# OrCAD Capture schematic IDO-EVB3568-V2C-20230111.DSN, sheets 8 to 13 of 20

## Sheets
8 P08. SPK+MIC: size A3; title: IDO-EVB3568-V2; note: SPK + MIC
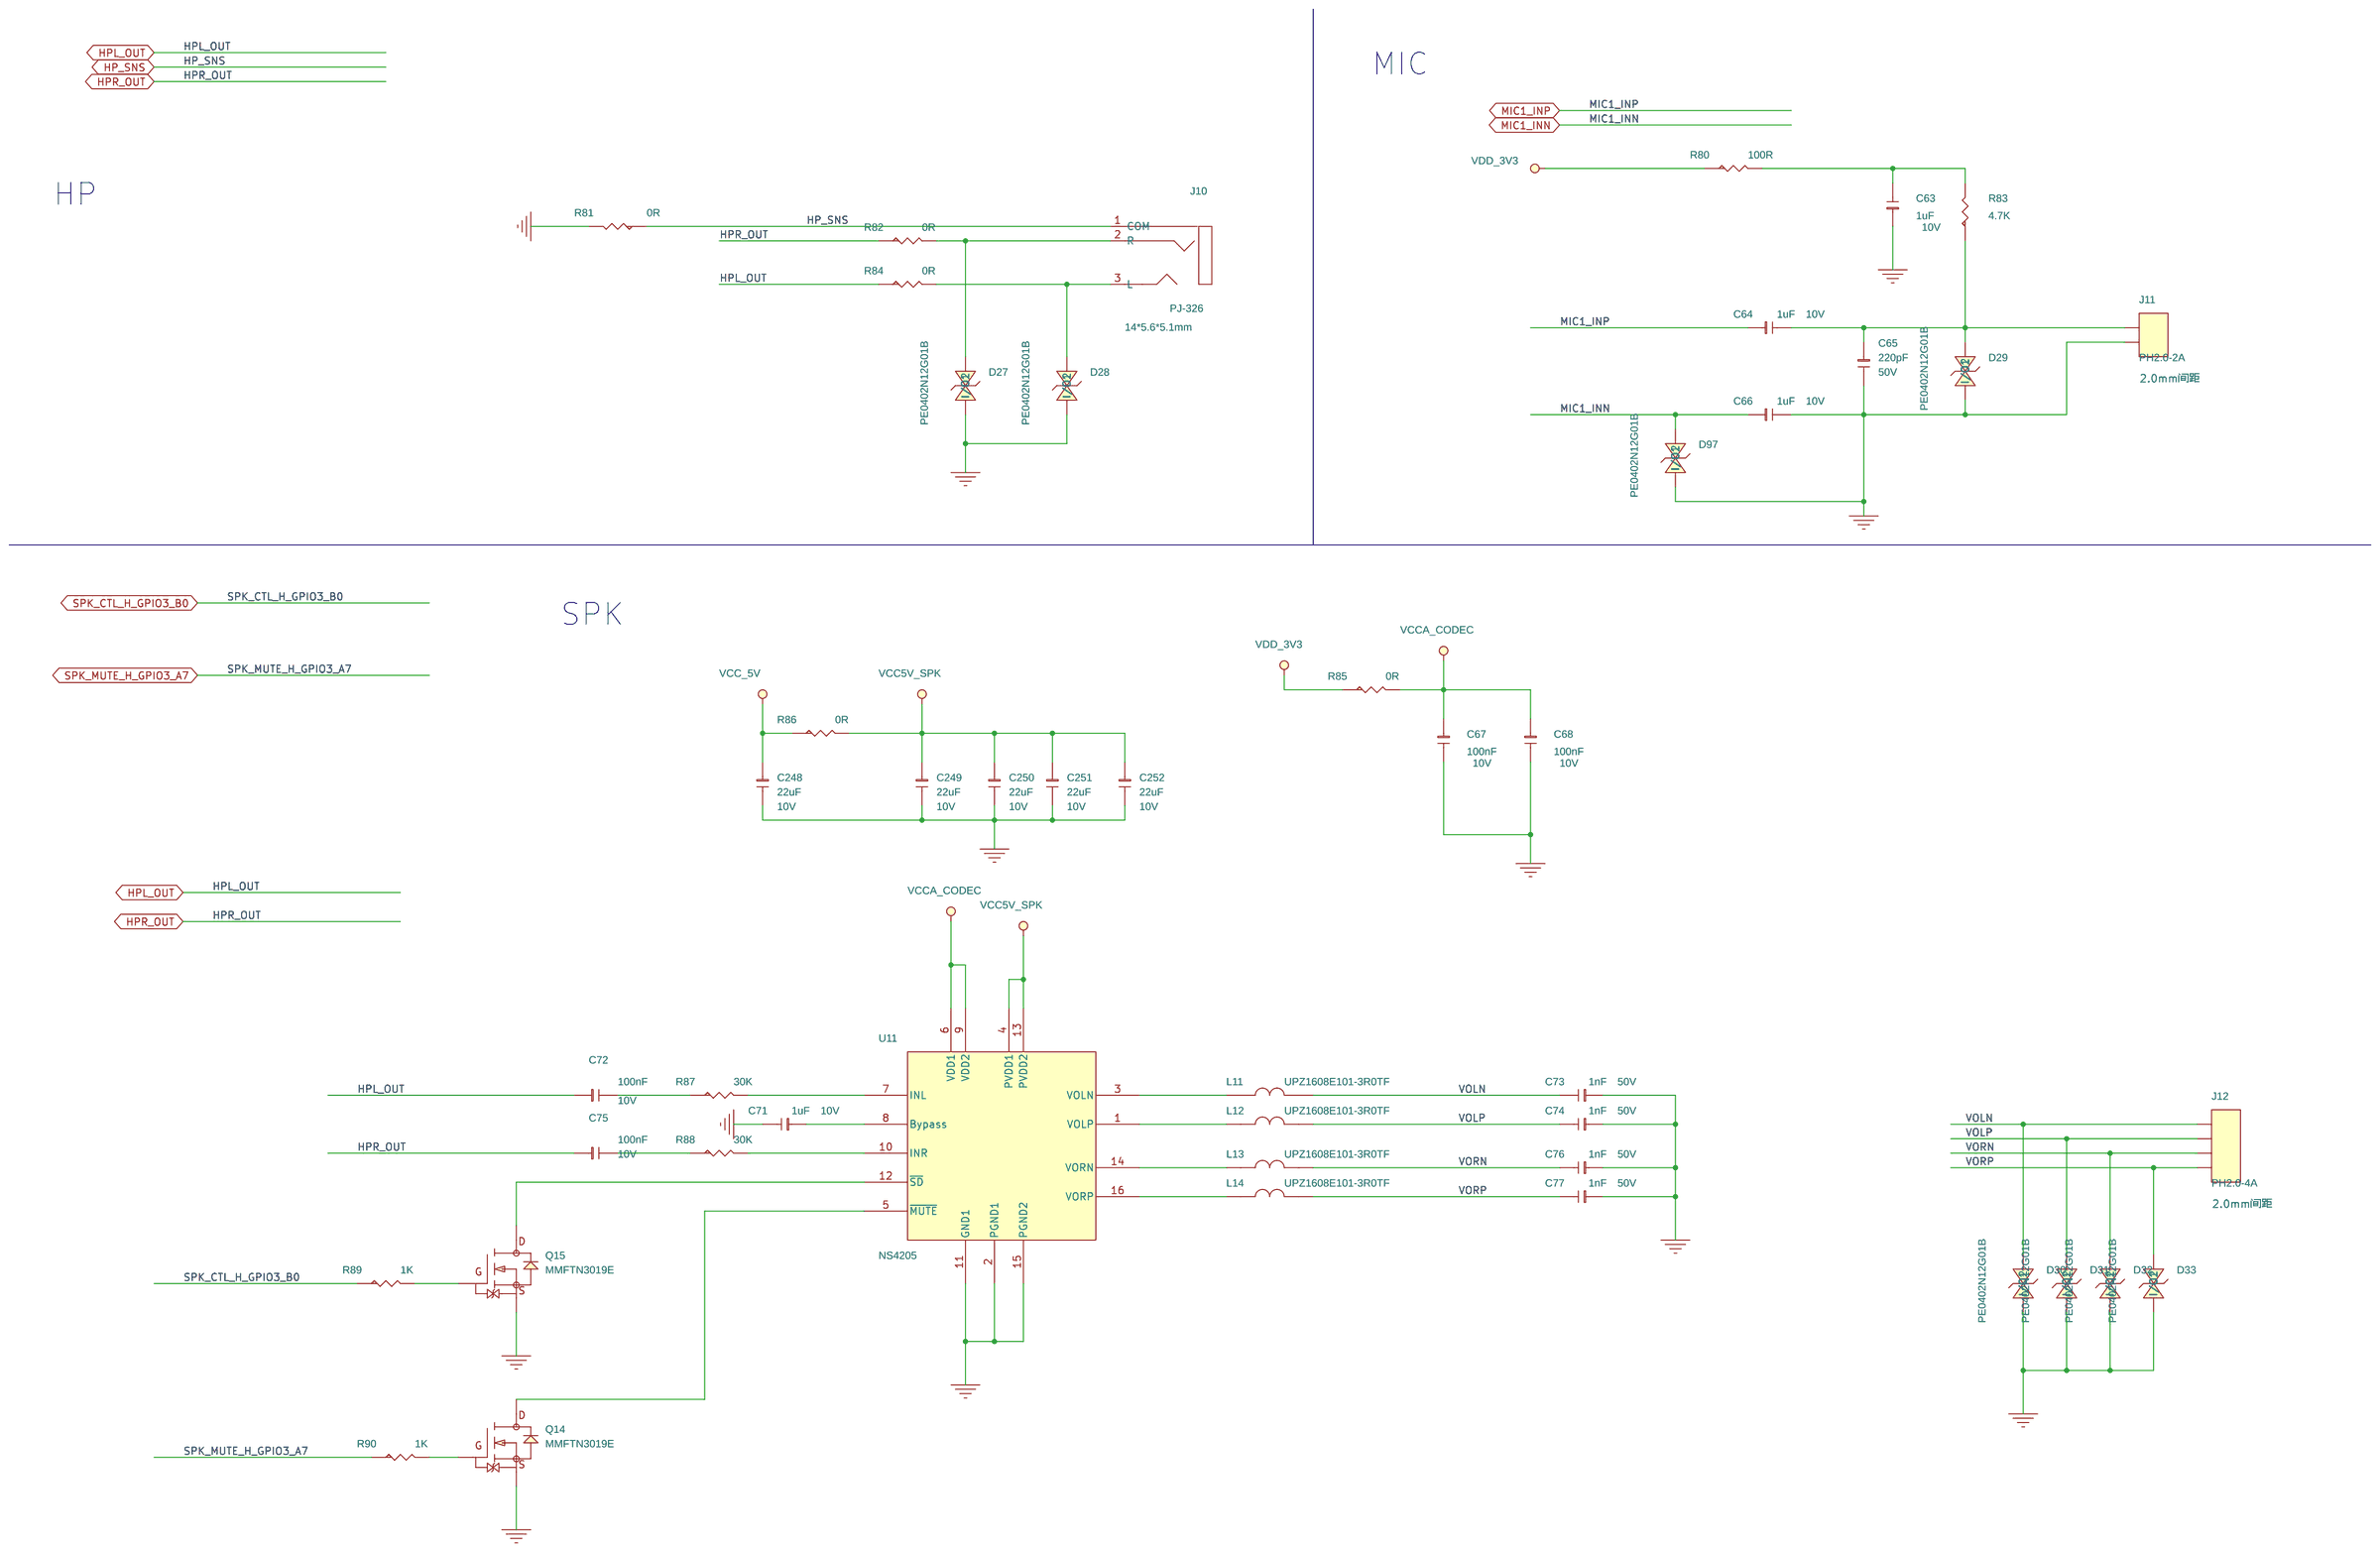
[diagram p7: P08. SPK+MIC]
9 P09. VO-MIPI-TX1: size A4; title: IDO-EVB3568-V2; note: VO-LCM_MIPI_DSI_TX1
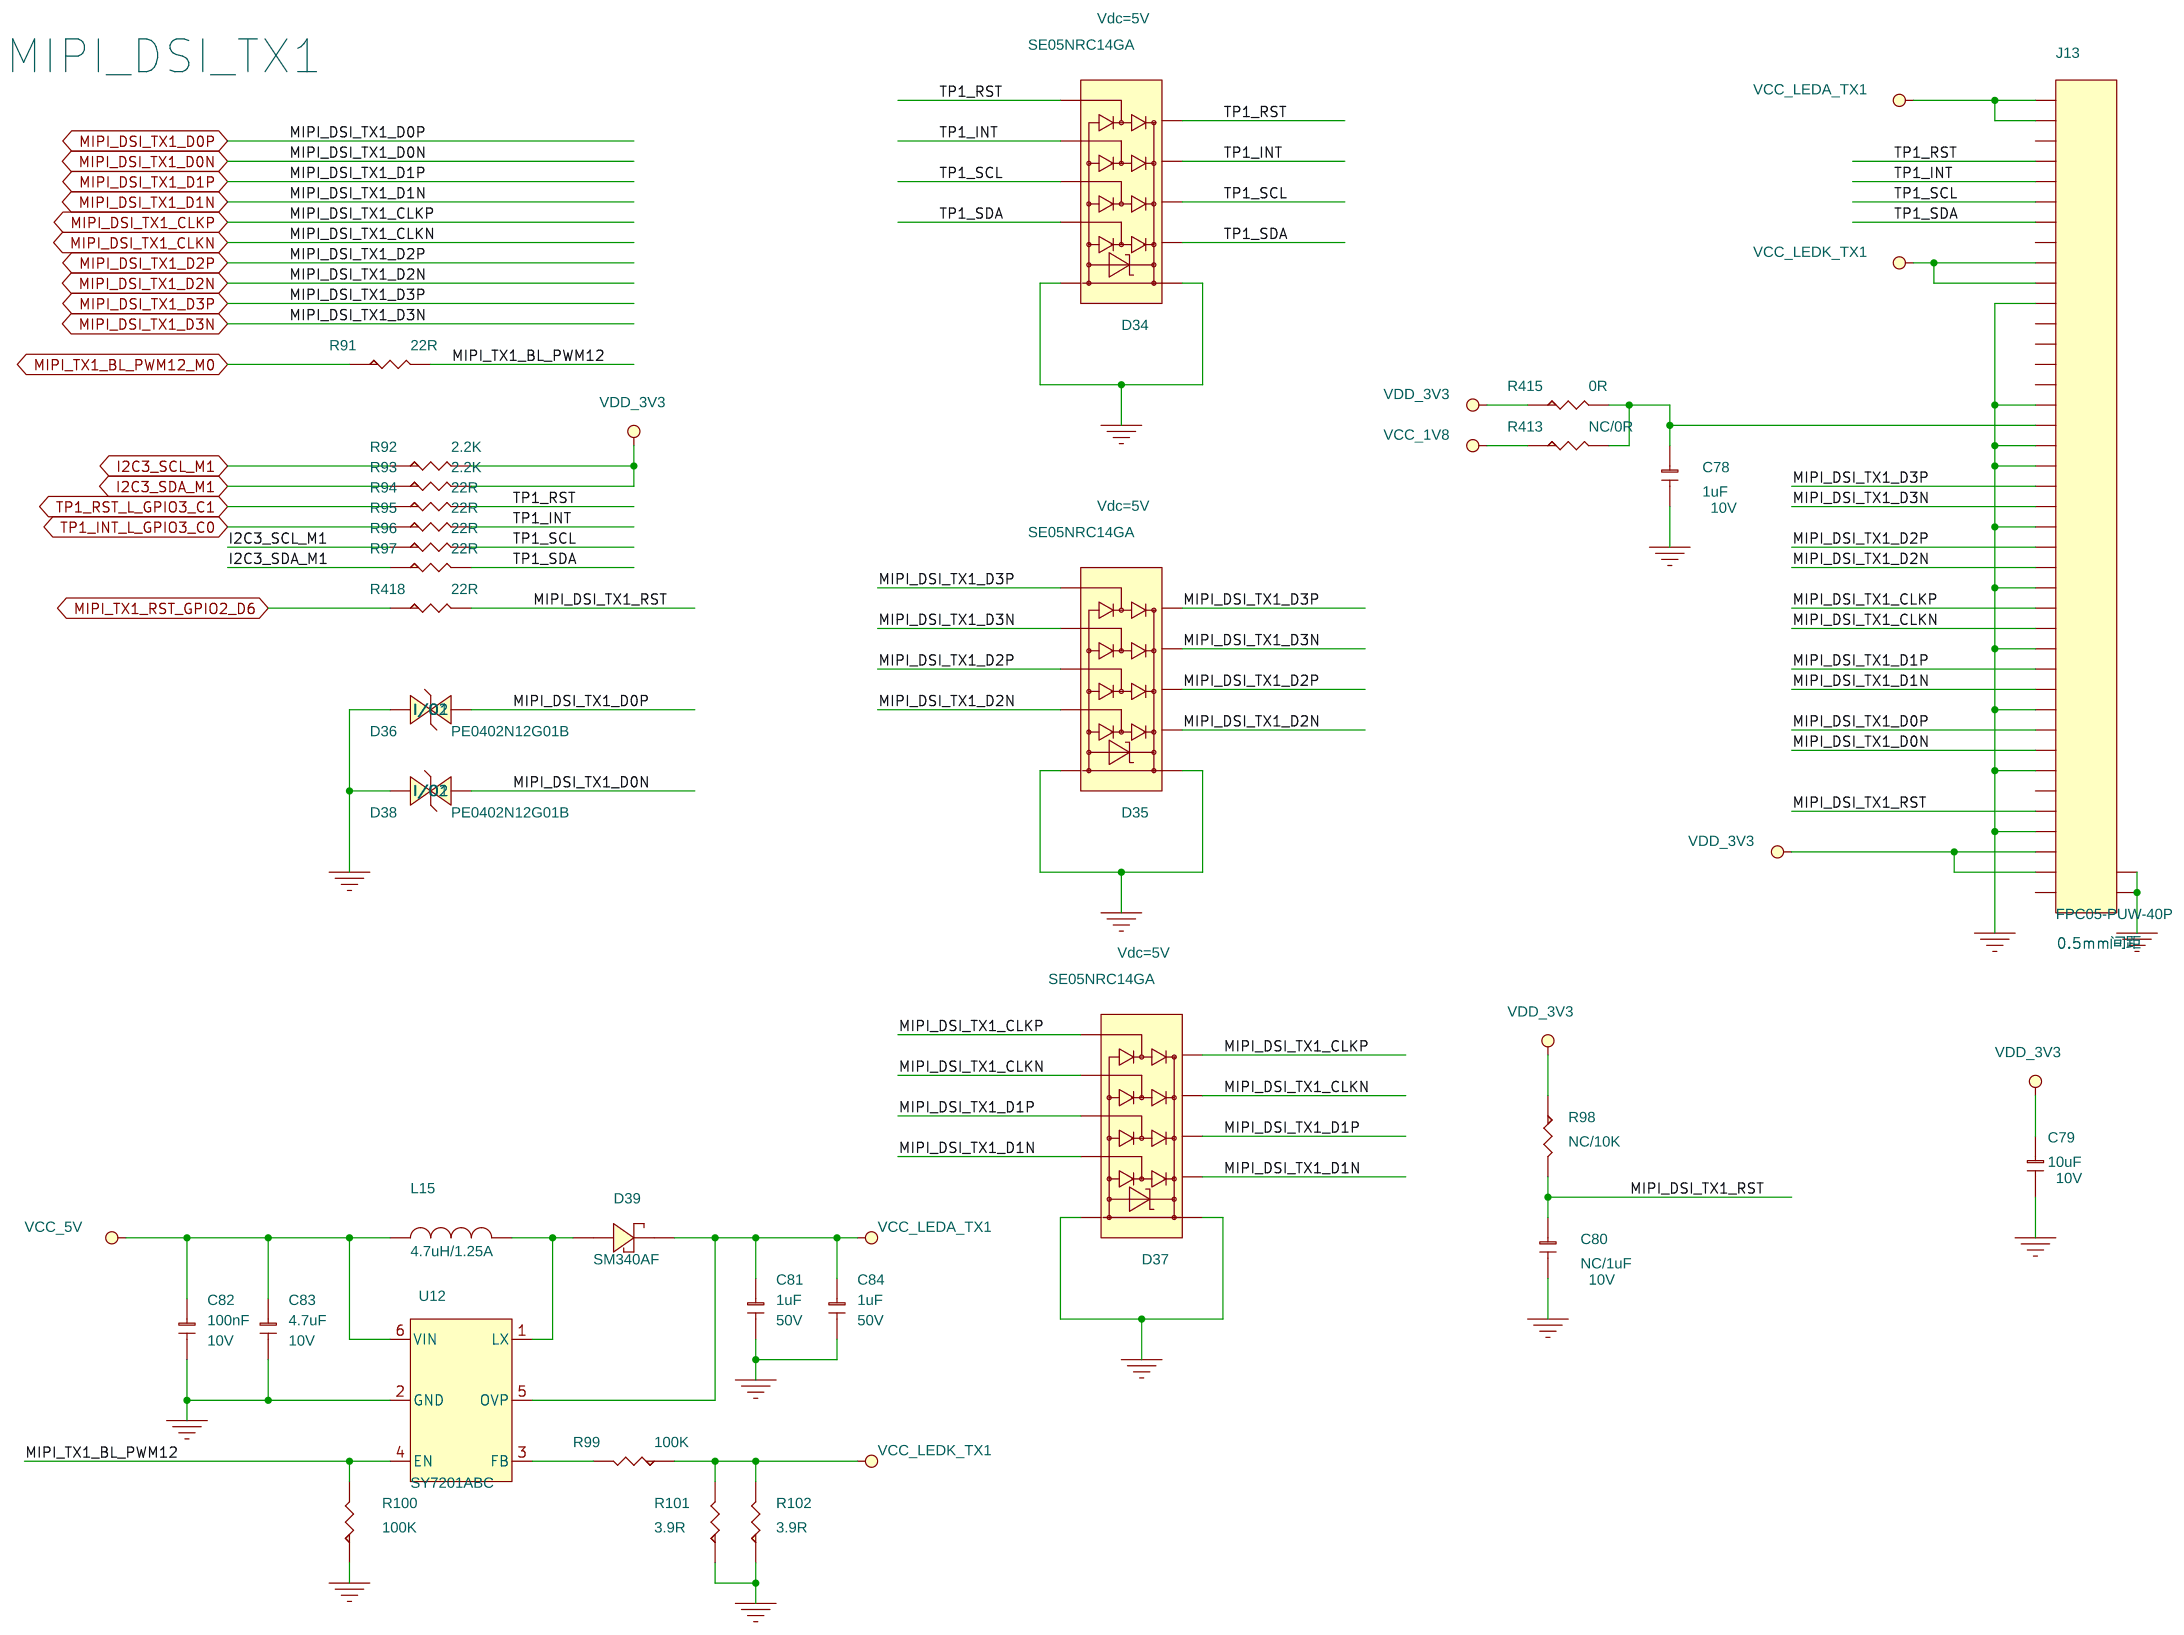
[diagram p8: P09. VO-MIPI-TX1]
10 P10. VO-HDMI2.0 TX: size A4; title: IDO-EVB3568-V2; note: VO-HDMI
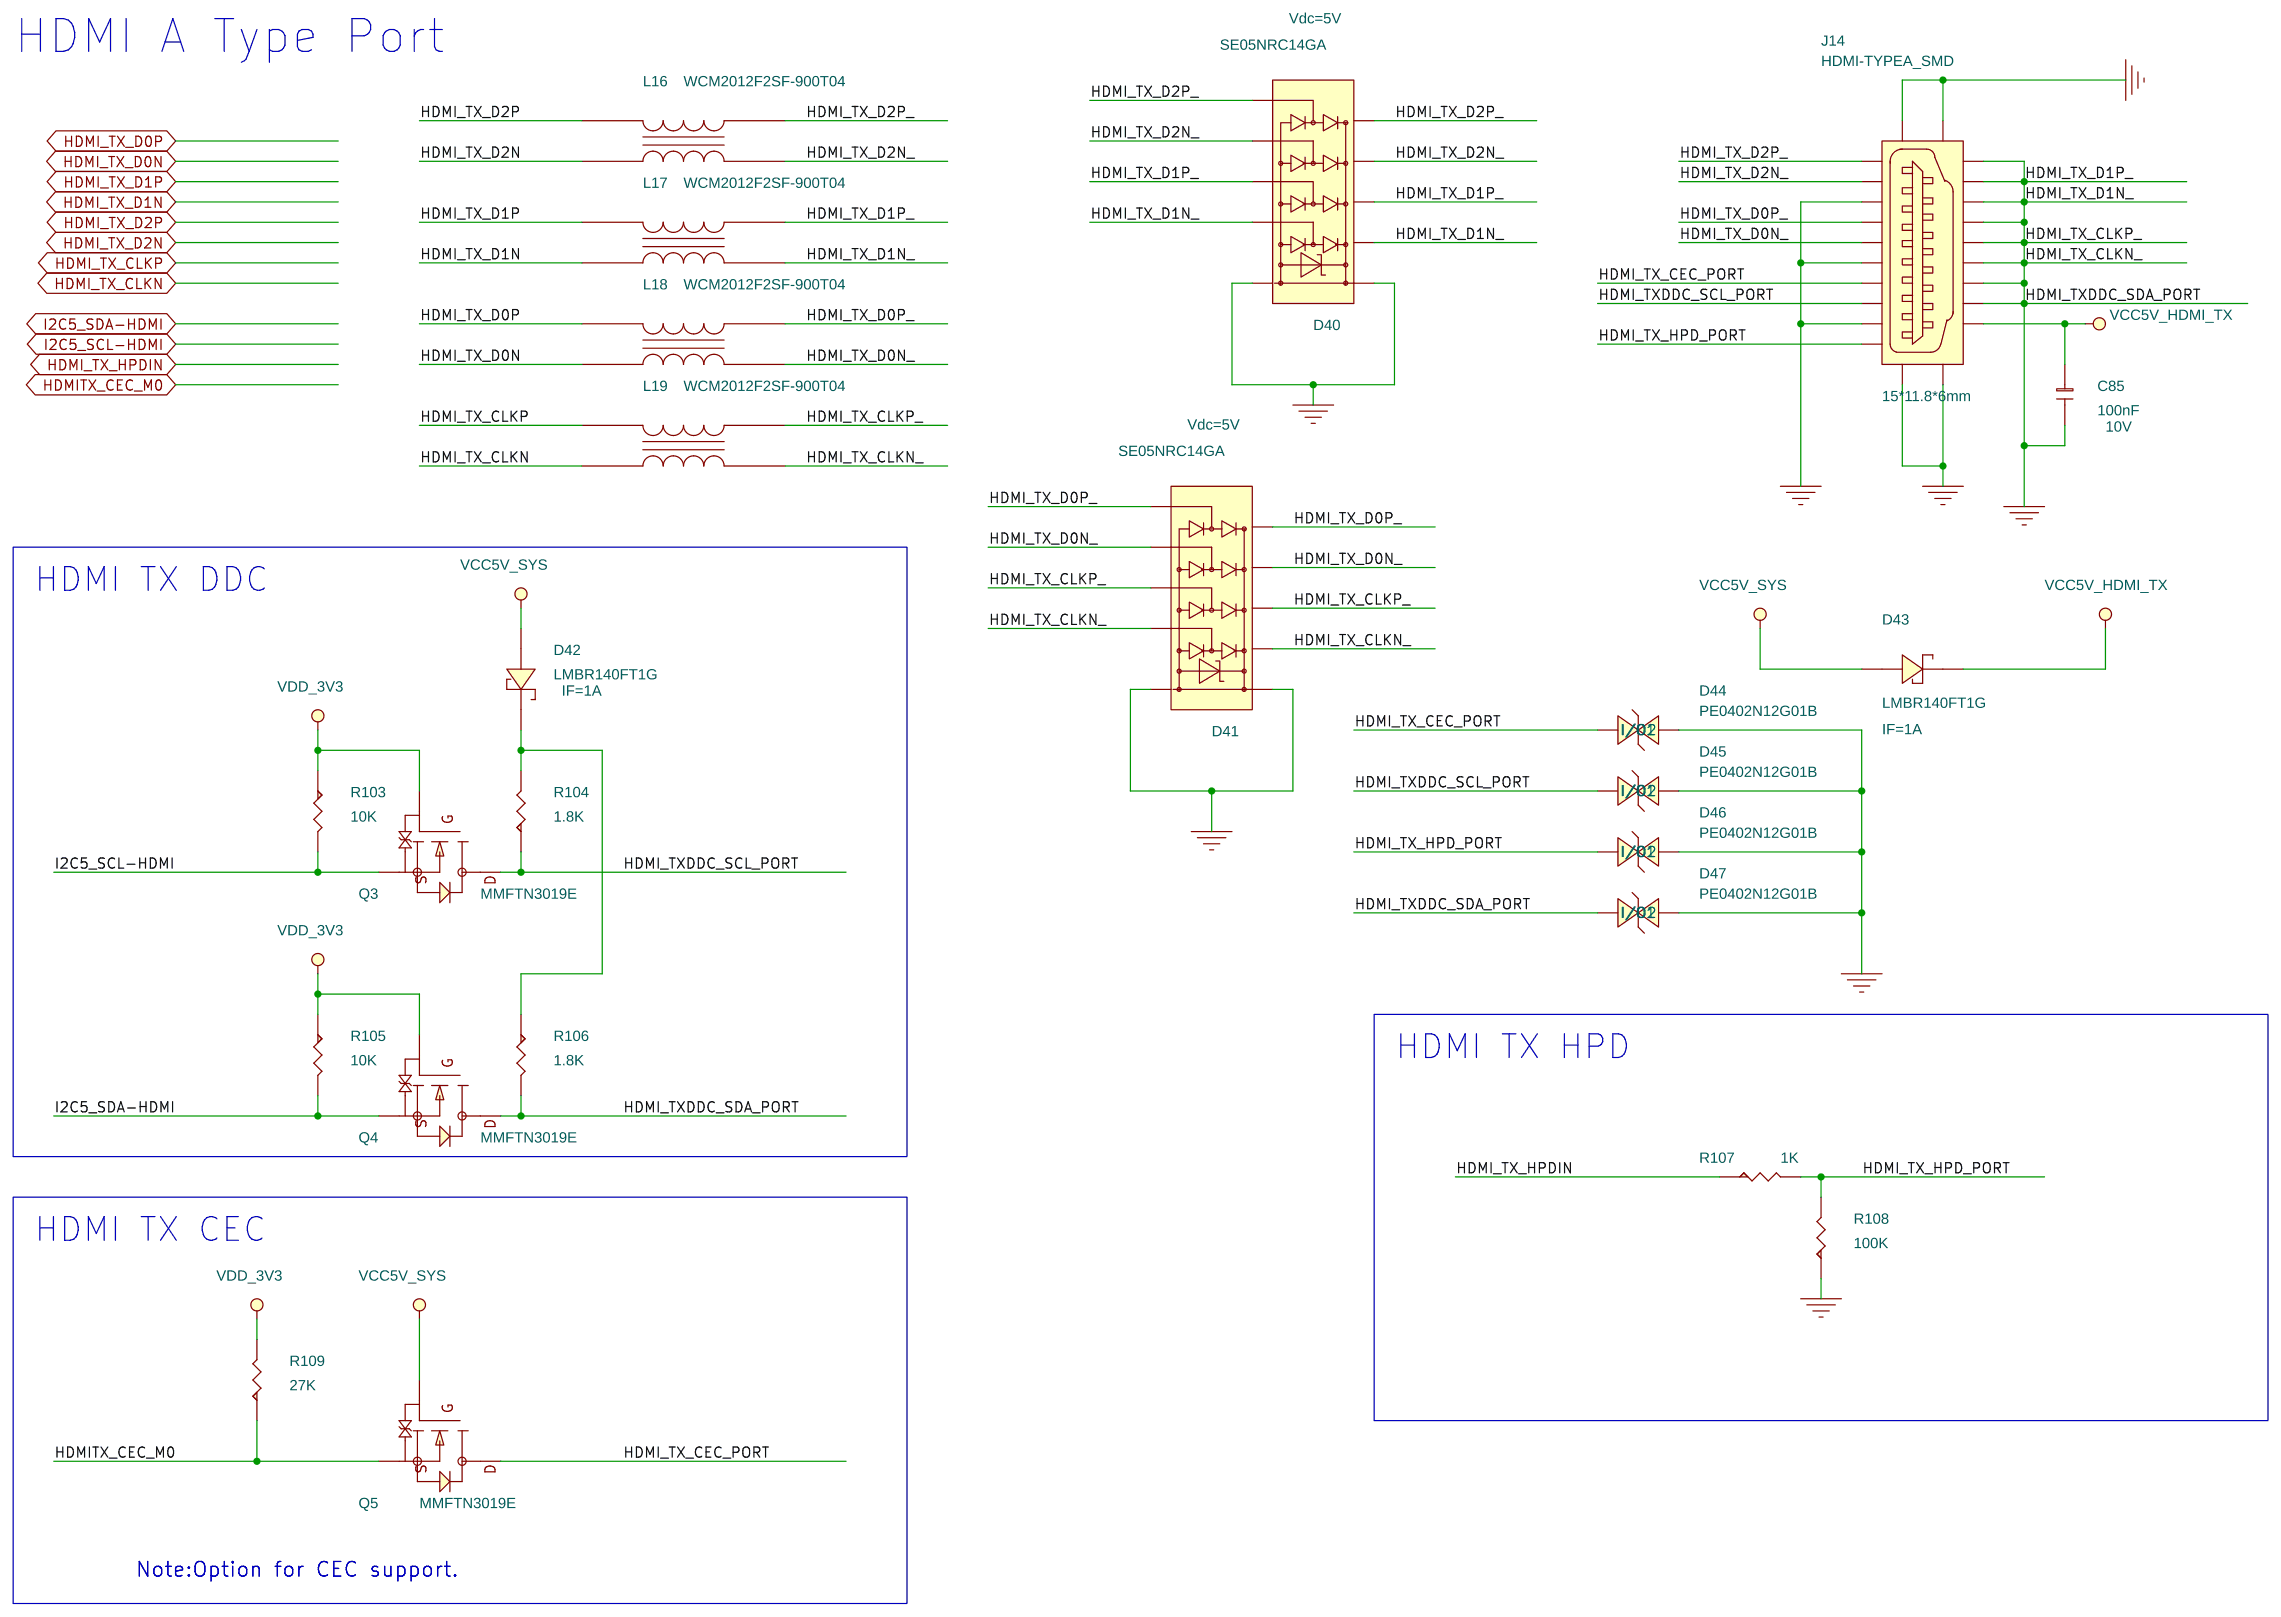
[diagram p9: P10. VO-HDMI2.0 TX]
11 P11. VO-LCM_LVDS_TX0: size A2; title: IDO-EVB3568-V2; note: VO-LCM_LVDS TX
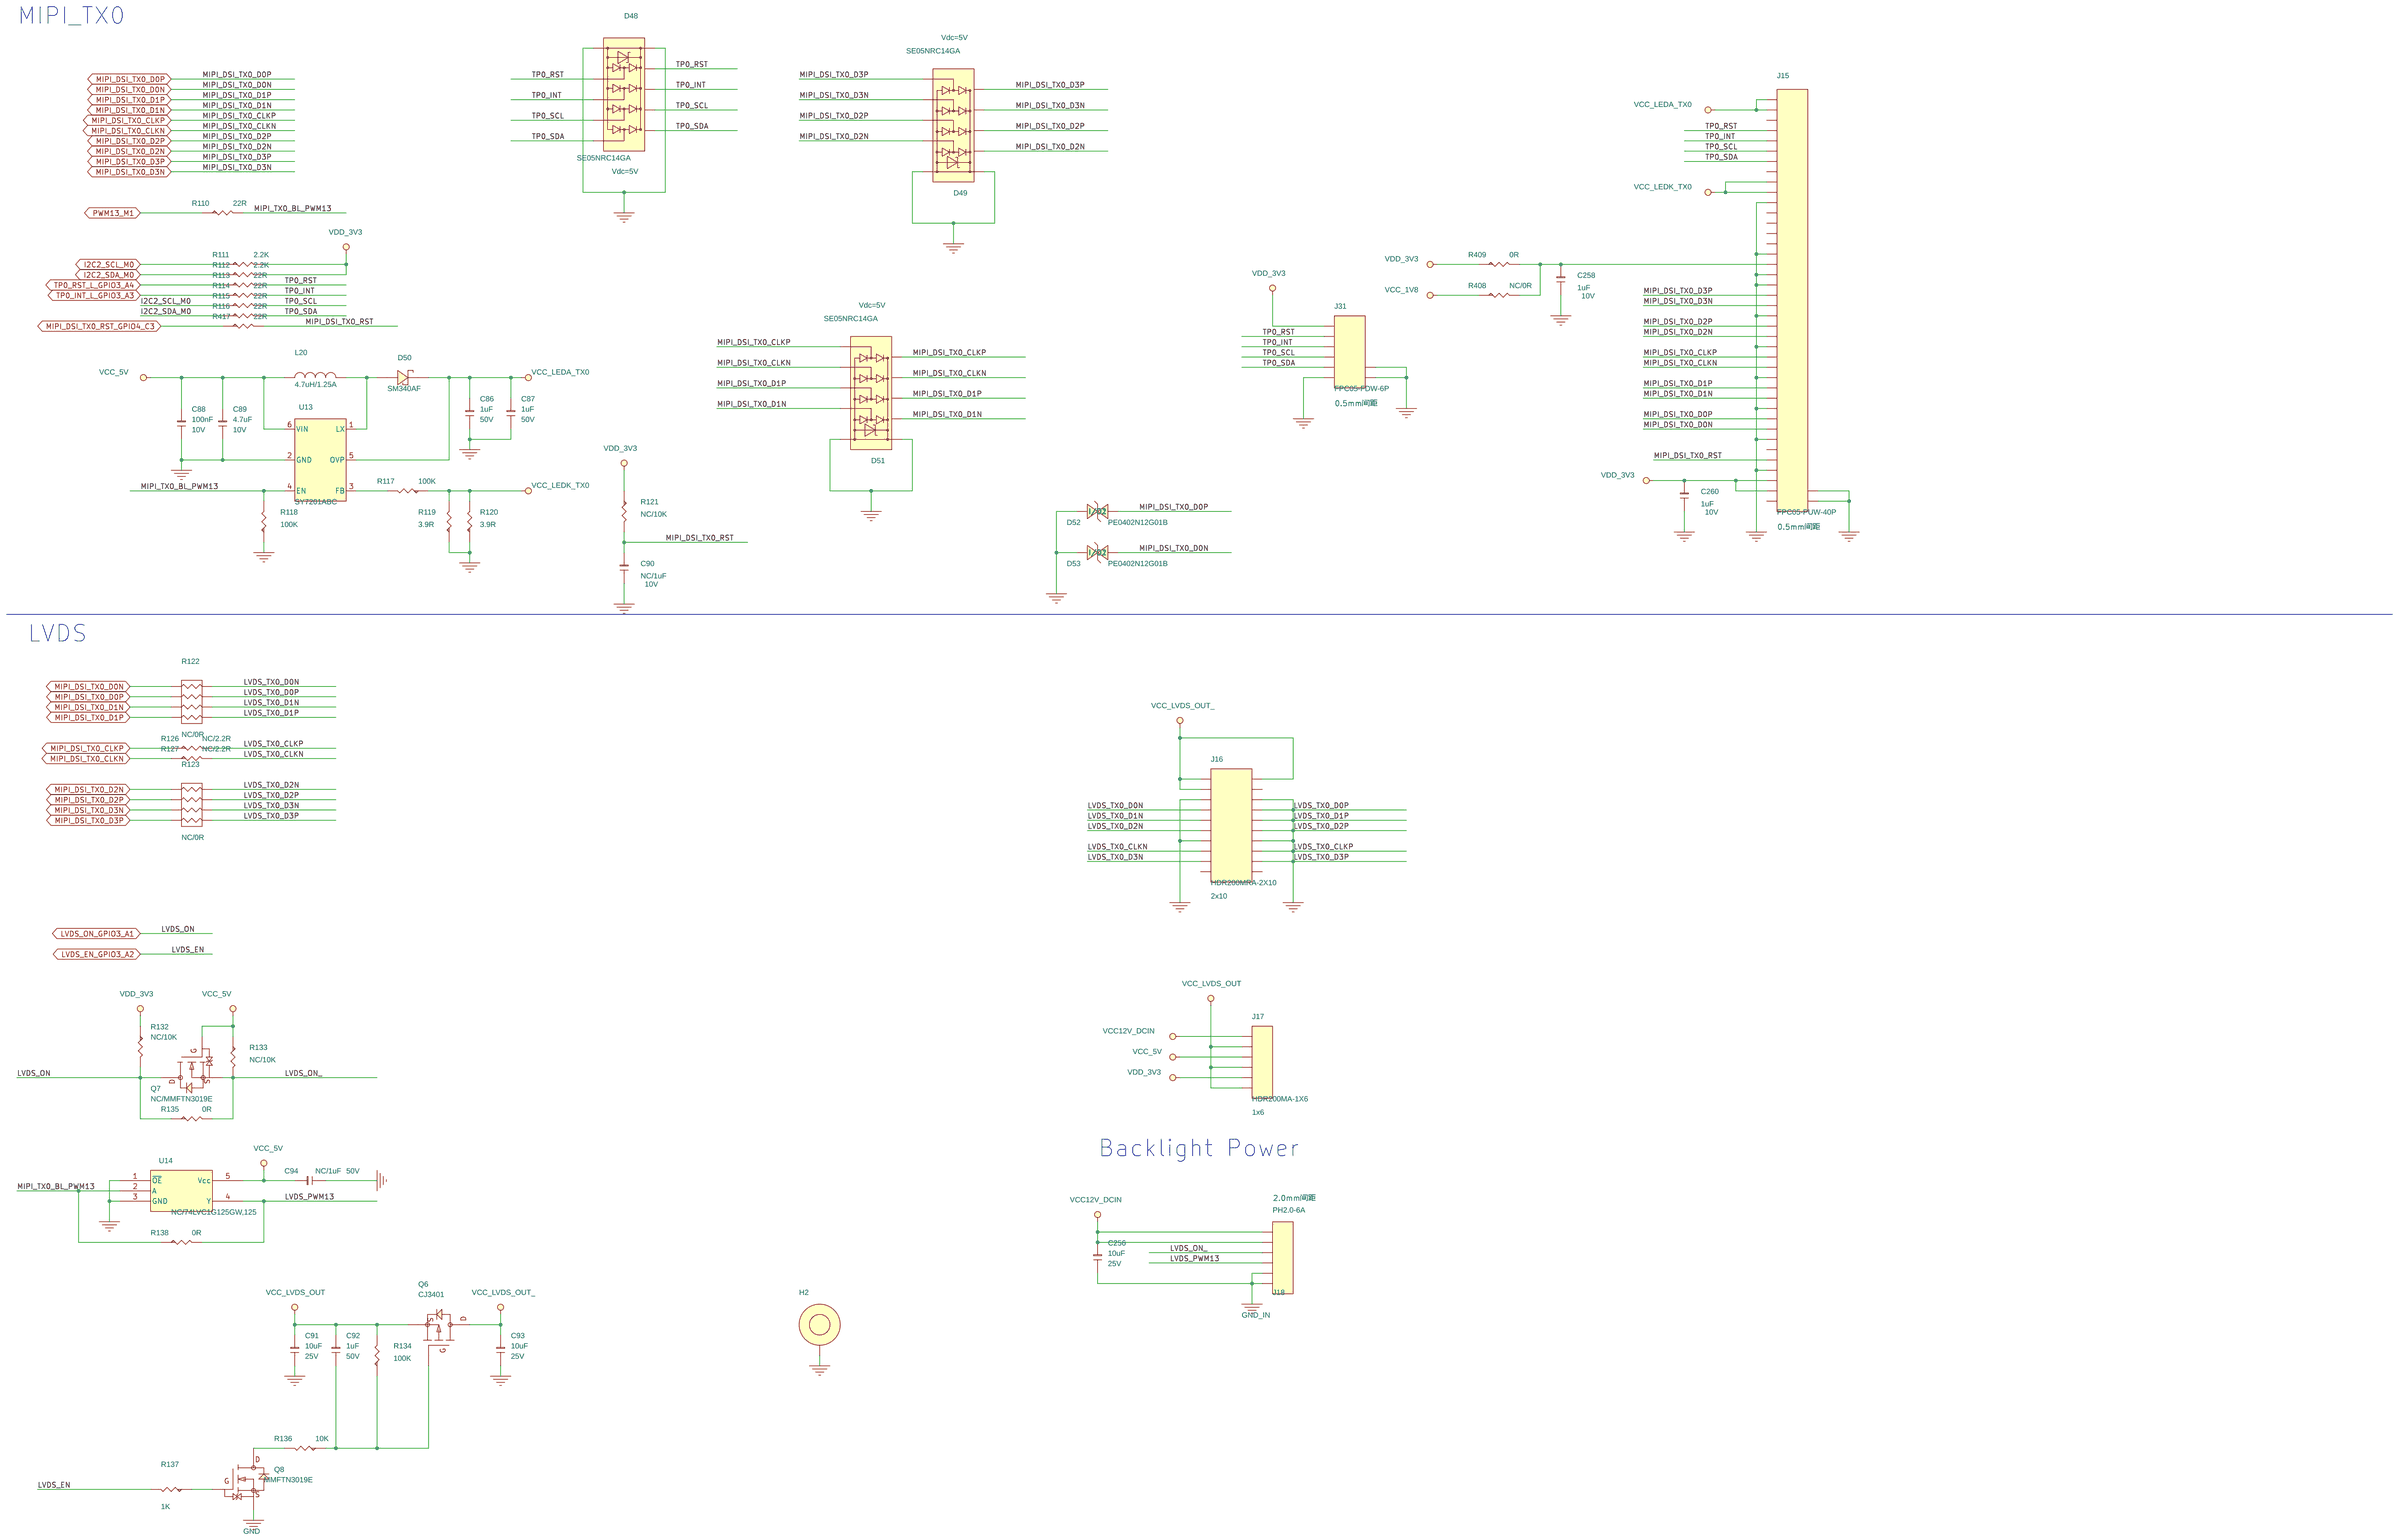
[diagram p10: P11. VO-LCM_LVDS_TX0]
12 P12. VI-MIPI-CSI: size A3; title: IDO-EVB3568-V2; note: VI-MIPI-CSI
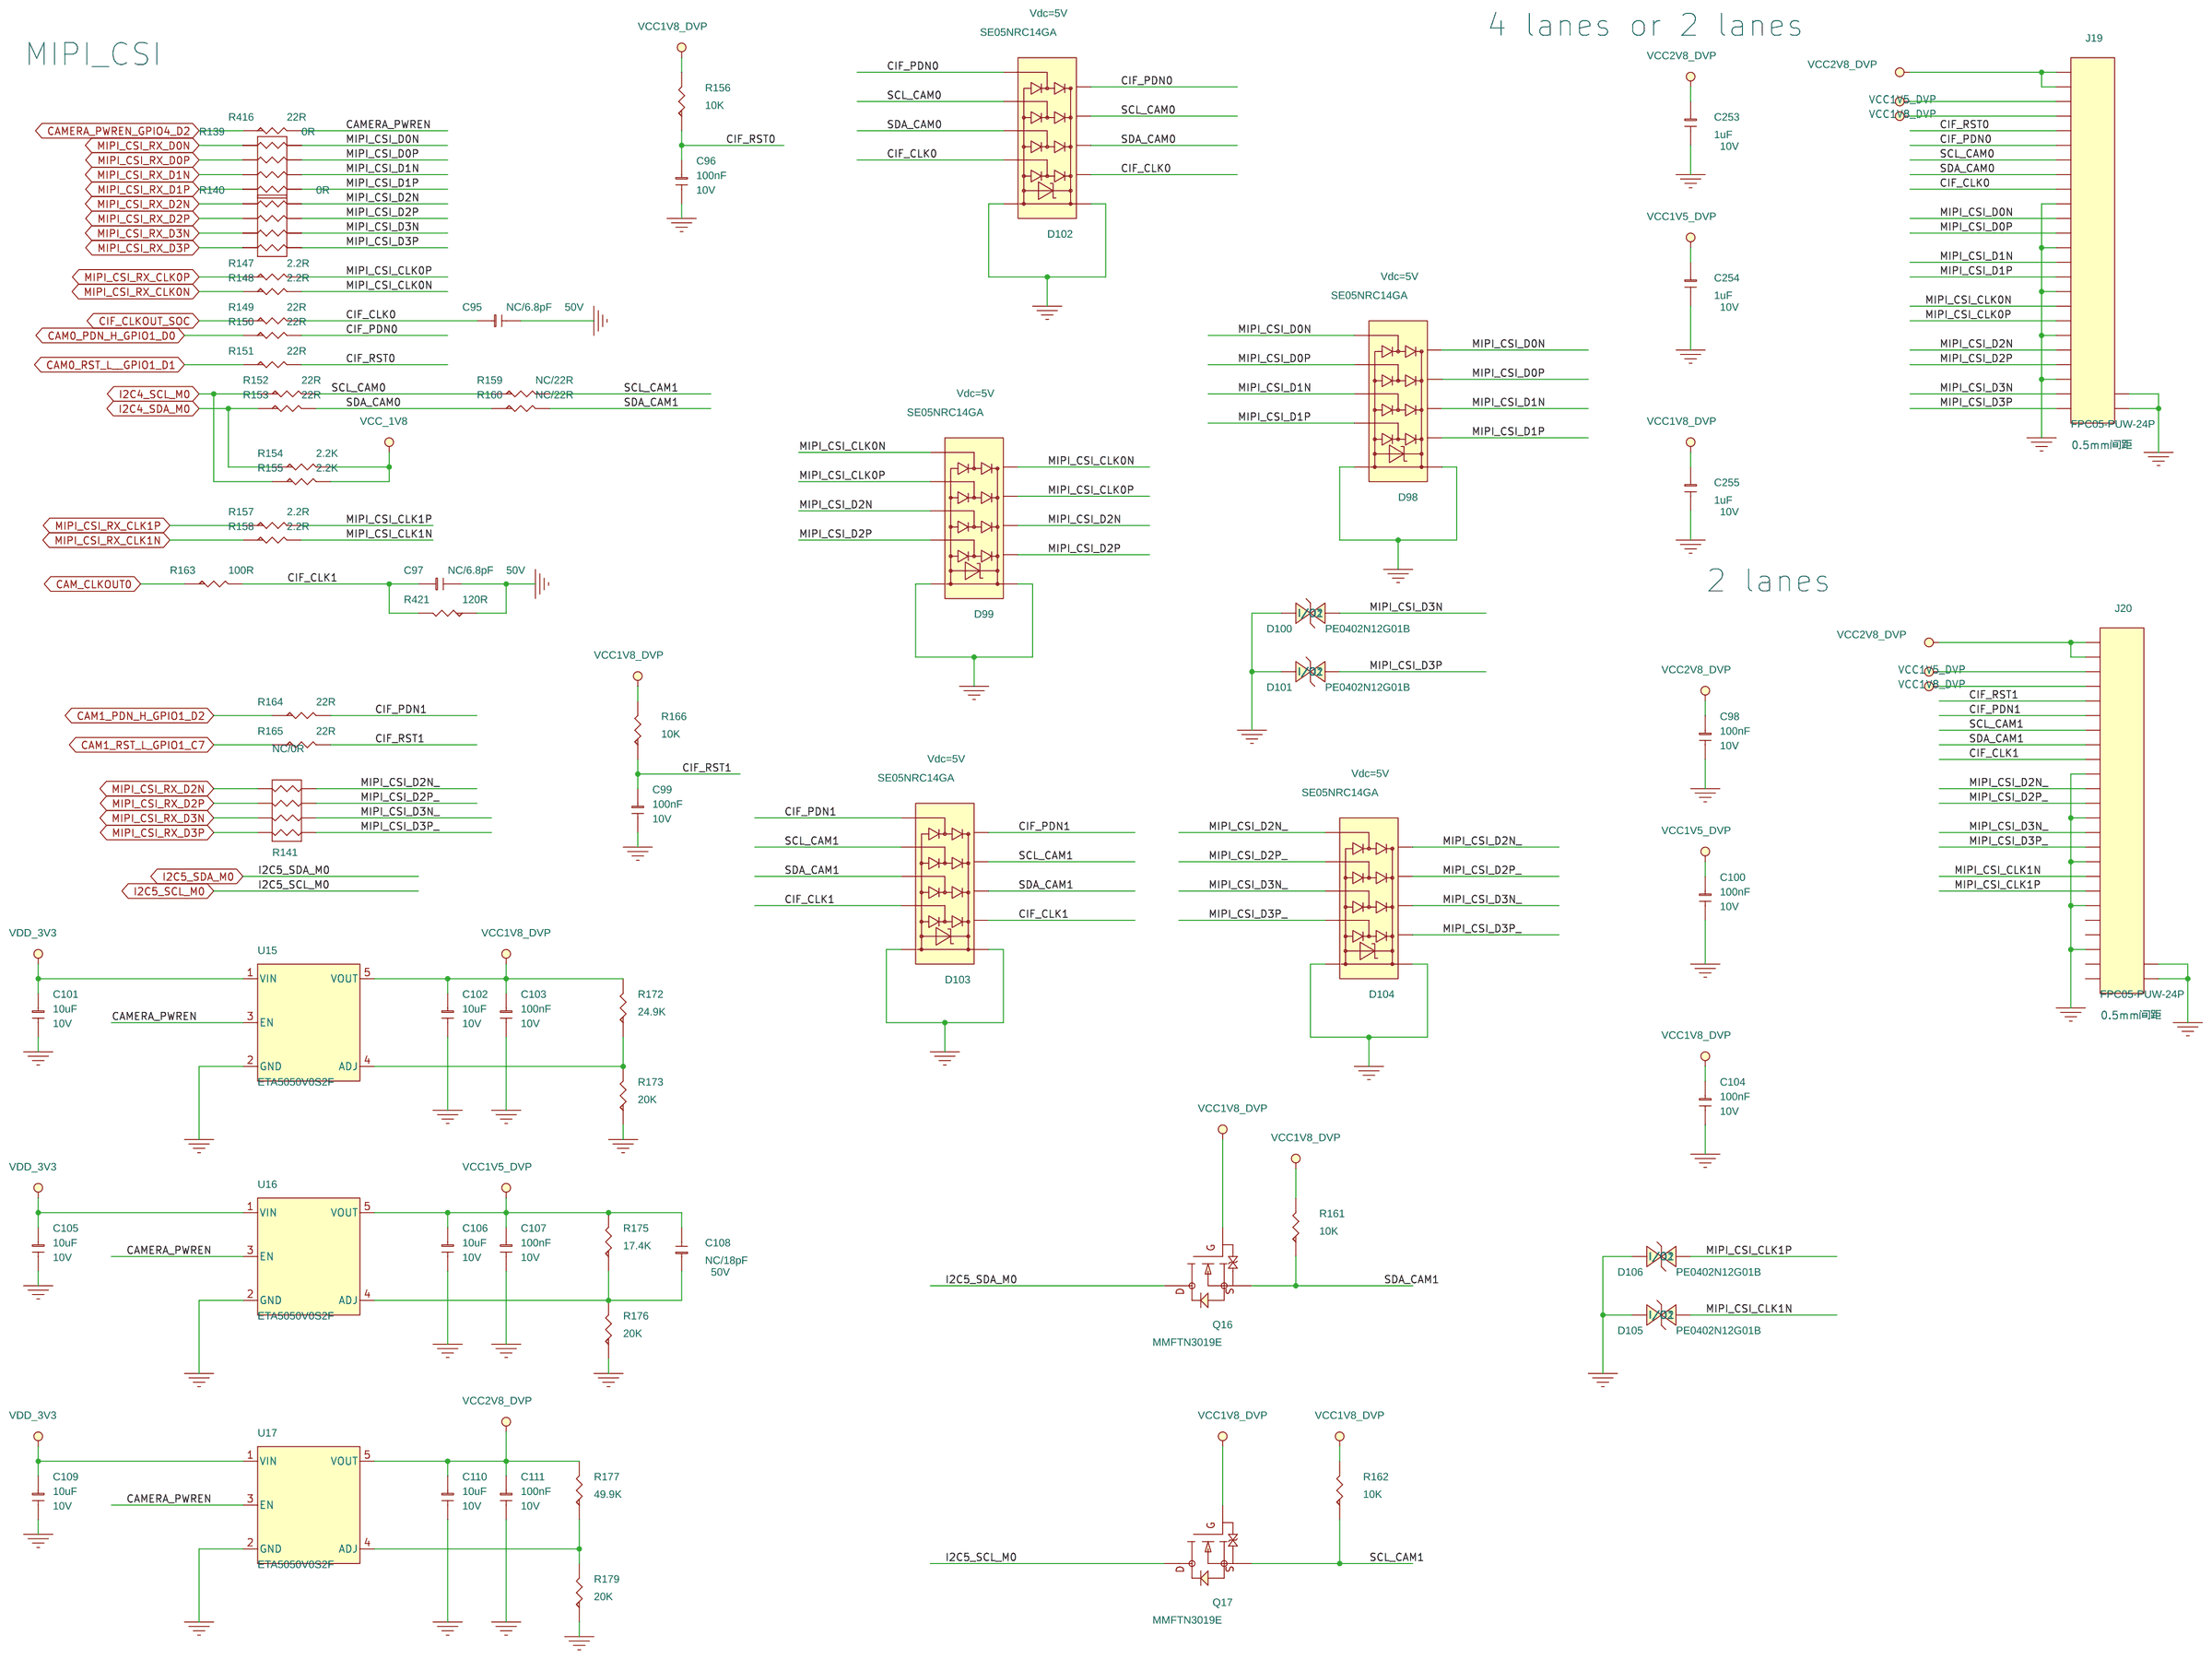
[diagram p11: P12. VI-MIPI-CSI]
13 P14. Ethernet-GEPHY_RGMII0: size A2; title: IDO-EVB3568-V2; note: Ethernet-GEPHY_RGMII0
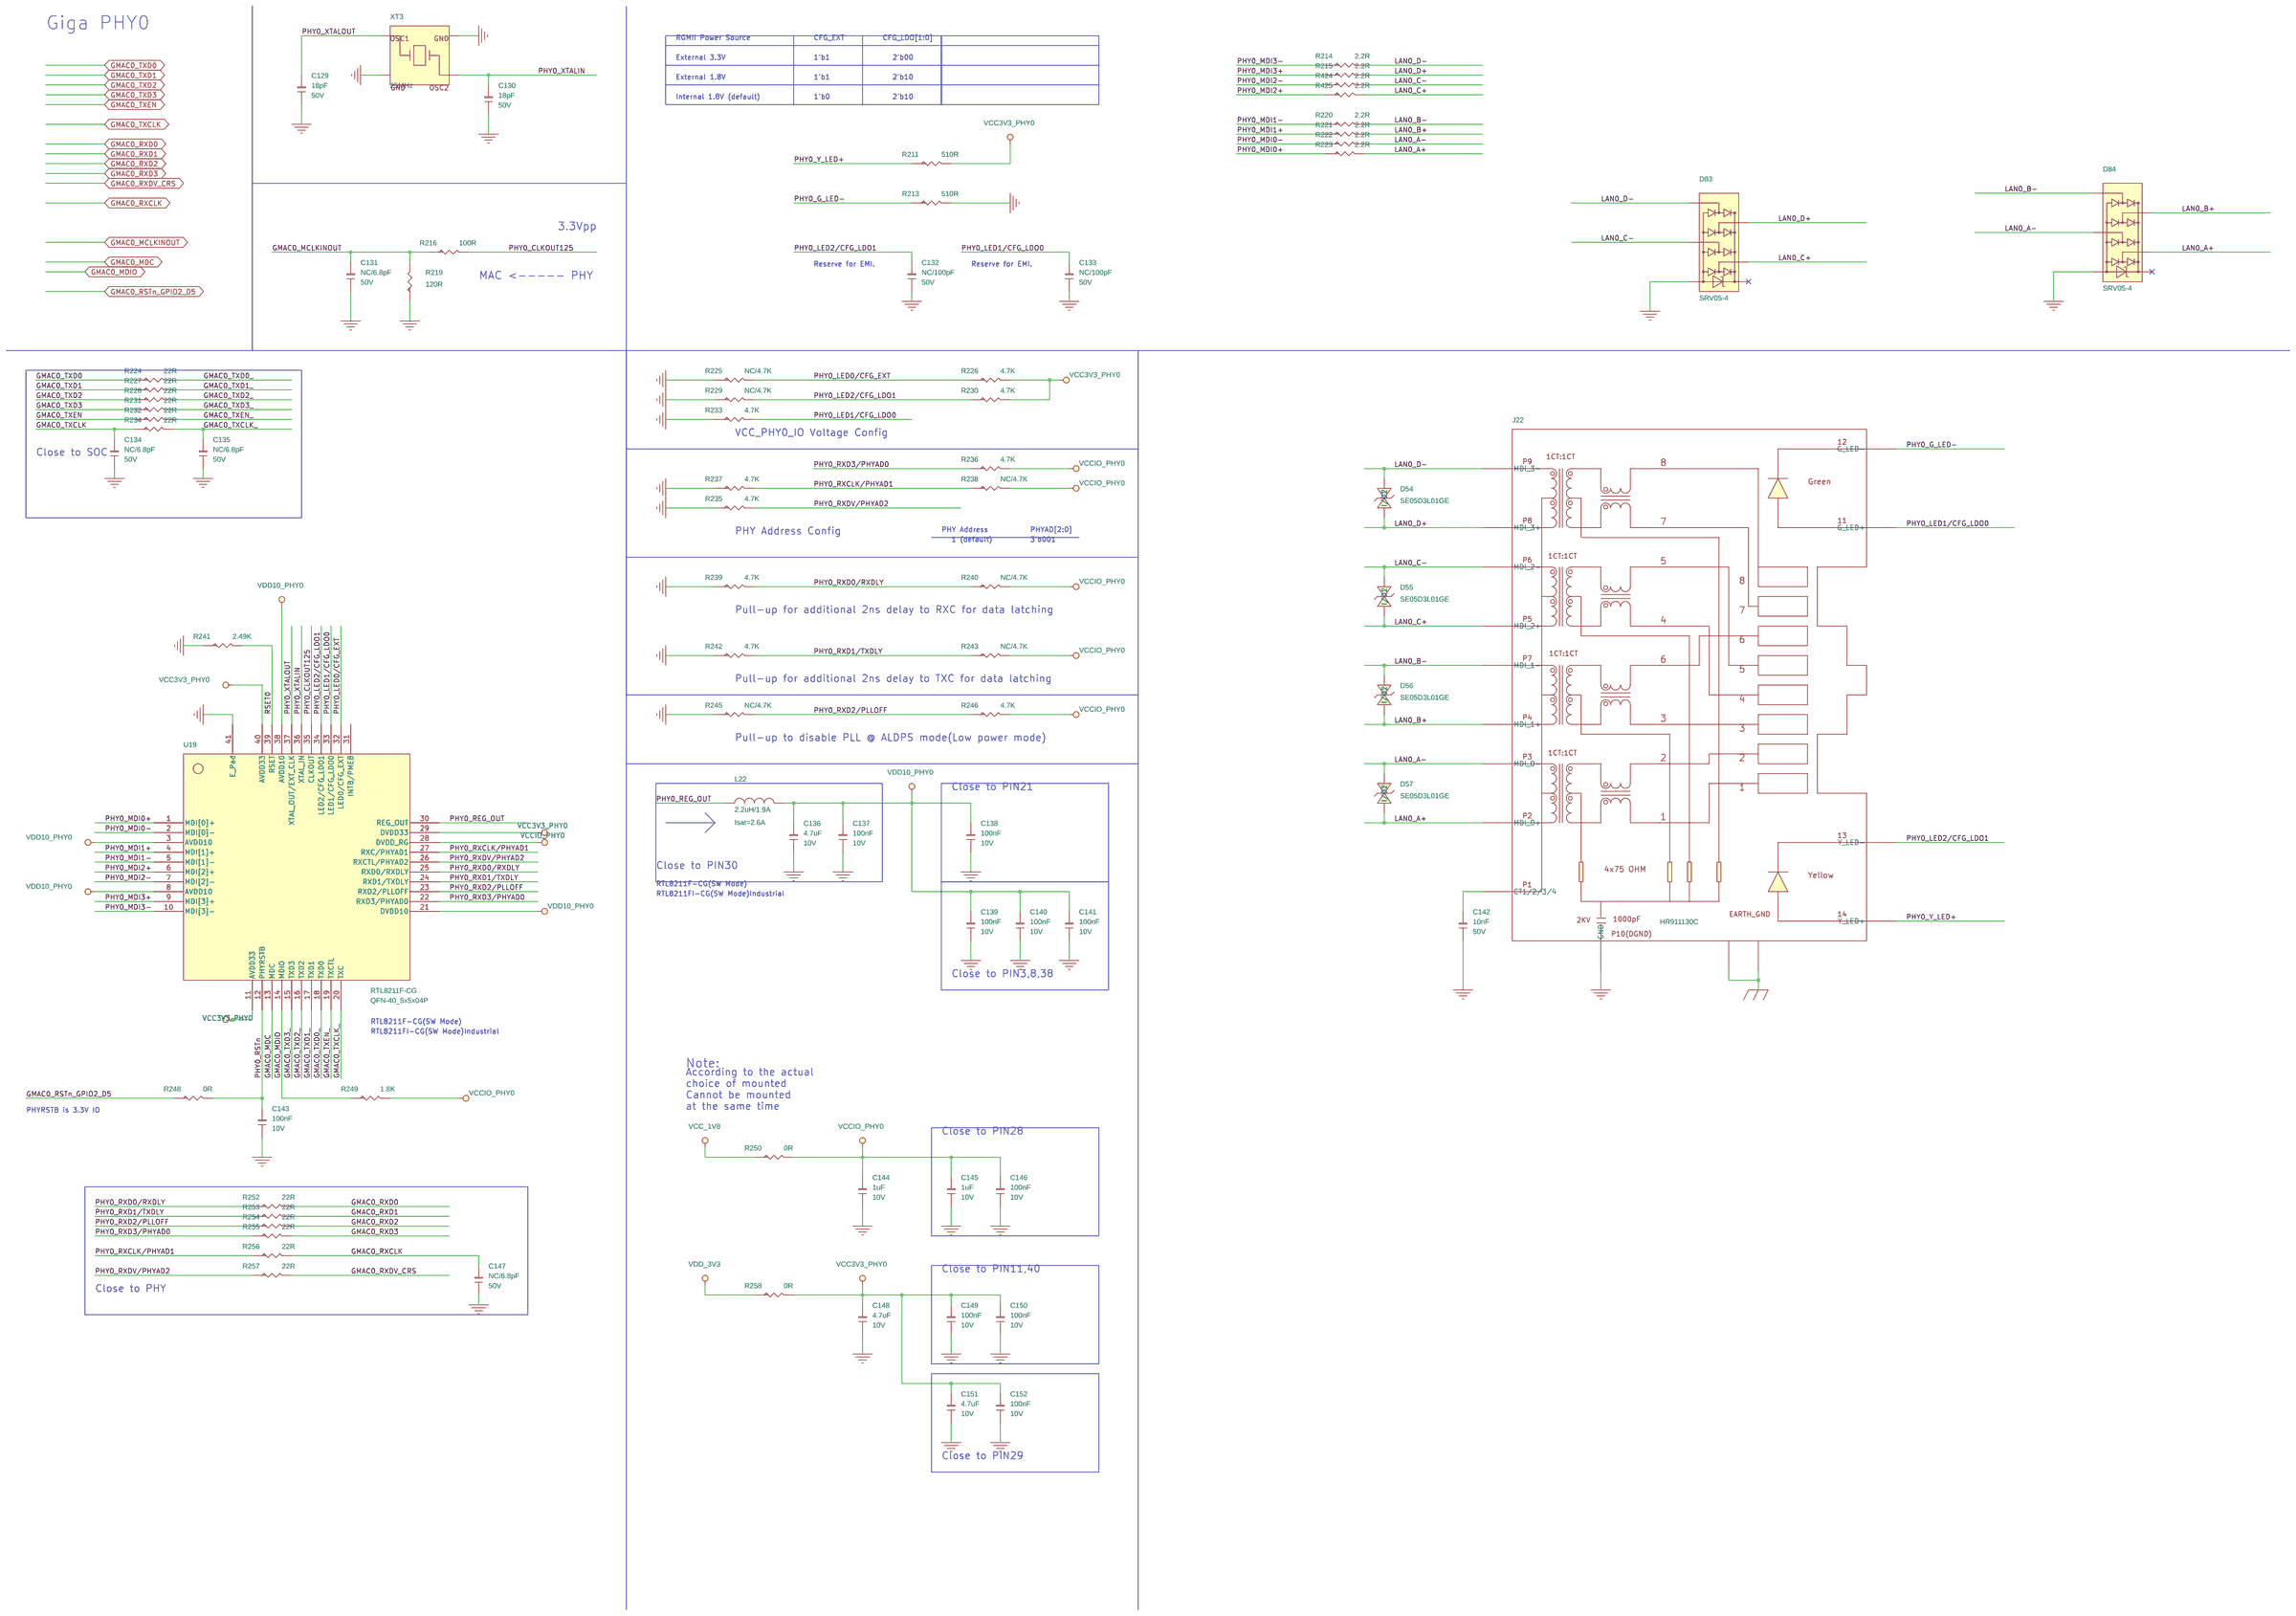
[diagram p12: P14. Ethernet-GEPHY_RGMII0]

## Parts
sheet P08. SPK+MIC
C63  1uF  [C0402]
C64  1uF  [C0402]
C65  220pF  [C0402]
C66  1uF  [C0402]
C67  100nF  [C0402]
C68  100nF  [C0402]
C71  1uF  [C0402]
C72  100nF  [C0402]
C73  1nF  [C0402]
C74  1nF  [C0402]
C75  100nF  [C0402]
C76  1nF  [C0402]
C77  1nF  [C0402]
C248  22uF  [C0603]
C249  22uF  [C0603]
C250  22uF  [C0603]
C251  22uF  [C0603]
C252  22uF  [C0603]
D27  PE0402N12G01B  [V0402]
D28  PE0402N12G01B  [V0402]
D29  PE0402N12G01B  [V0402]
D30  PE0402N12G01B  [V0402]
D31  PE0402N12G01B  [V0402]
D32  PE0402N12G01B  [V0402]
D33  PE0402N12G01B  [V0402]
D97  PE0402N12G01B  [V0402]
J10  PJ-326  [PJ-326A-3P]
J11  PH2.0-2A  [PH200-2A]
J12  PH2.0-4A  [PH200-4A]
L11  UPZ1608E101-3R0TF  [L0603]
L12  UPZ1608E101-3R0TF  [L0603]
L13  UPZ1608E101-3R0TF  [L0603]
L14  UPZ1608E101-3R0TF  [L0603]
Q14  MMFTN3019E  [SOT523]
Q15  MMFTN3019E  [SOT523]
R80  100R  [R0402]
R81  0R  [R0402]
R82  0R  [R0402]
R83  4.7K  [R0402]
R84  0R  [R0402]
R85  0R  [R0603]
R86  0R  [R0805]
R87  30K  [R0402]
R88  30K  [R0402]
R89  1K  [R0402]
R90  1K  [R0402]
U11  NS4205  [SOP16-P127-390X990]
sheet P09. VO-MIPI-TX1
C78  1uF  [C0402]
C79  10uF  [C0603]
C80  NC/1uF  [C0402]
C81  1uF  [C0603]
C82  100nF  [C0402]
C83  4.7uF  [C0402]
C84  1uF  [C0603]
D34  SE05NRC14GA  [DFN2510-10L]
D35  SE05NRC14GA  [DFN2510-10L]
D36  PE0402N12G01B  [V0402]
D37  SE05NRC14GA  [DFN2510-10L]
D38  PE0402N12G01B  [V0402]
D39  SM340AF  [SMAF]
J13  FPC05-PUW-40P  [FPC05-40P]
L15  4.7uH/1.25A  [IND_252012]
R91  22R  [R0402]
R92  2.2K  [R0402]
R93  2.2K  [R0402]
R94  22R  [R0402]
R95  22R  [R0402]
R96  22R  [R0402]
R97  22R  [R0402]
R98  NC/10K  [R0402]
R99  100K  [R0402]
R100  100K  [R0402]
R101  3.9R  [R0603]
R102  3.9R  [R0603]
R413  NC/0R  [R0402]
R415  0R  [R0402]
R418  22R  [R0402]
U12  SY7201ABC  [SOT23-6]
sheet P10. VO-HDMI2.0 TX
C85  100nF  [C0402]
D40  SE05NRC14GA  [DFN2510-10L]
D41  SE05NRC14GA  [DFN2510-10L]
D42  LMBR140FT1G  [SOD-123F]
D43  LMBR140FT1G  [SOD-123F]
D44  PE0402N12G01B  [V0402]
D45  PE0402N12G01B  [V0402]
D46  PE0402N12G01B  [V0402]
D47  PE0402N12G01B  [V0402]
J14  HDMI-TYPEA_SMD  [HDMI-TYPEA_SMD]
L16  WCM2012F2SF-900T04  [CMLS-ACM2012]
L17  WCM2012F2SF-900T04  [CMLS-ACM2012]
L18  WCM2012F2SF-900T04  [CMLS-ACM2012]
L19  WCM2012F2SF-900T04  [CMLS-ACM2012]
Q3  MMFTN3019E  [SOT523]
Q4  MMFTN3019E  [SOT523]
Q5  MMFTN3019E  [SOT523]
R103  10K  [R0402]
R104  1.8K  [R0402]
R105  10K  [R0402]
R106  1.8K  [R0402]
R107  1K  [R0402]
R108  100K  [R0402]
R109  27K  [R0402]
sheet P11. VO-LCM_LVDS_TX0
C86  1uF  [C0603]
C87  1uF  [C0603]
C88  100nF  [C0402]
C89  4.7uF  [C0402]
C90  NC/1uF  [C0402]
C91  10uF  [C0805]
C92  1uF  [C0603]
C93  10uF  [C0805]
C94  NC/1uF  [C0603]
C256  10uF  [C0805]
C258  1uF  [C0402]
C260  1uF  [C0402]
D48  SE05NRC14GA  [DFN2510-10L]
D49  SE05NRC14GA  [DFN2510-10L]
D50  SM340AF  [SMAF]
D51  SE05NRC14GA  [DFN2510-10L]
D52  PE0402N12G01B  [V0402]
D53  PE0402N12G01B  [V0402]
H2  HOLE  [MTG430_620_SMTSO_M3]
J15  FPC05-PUW-40P  [FPC05-40P]
J16  HDR200MRA-2X10  [HDR200MRA-2X10]
J17  HDR200MA-1X6  [HDR200MA-1X6]
J18  PH2.0-6A  [PH200-6A]
J31  FPC05-FDW-6P  [FPC05-6P]
L20  4.7uH/1.25A  [IND_252012]
Q6  CJ3401  [SOT23]
Q7  NC/MMFTN3019E  [SOT523]
Q8  MMFTN3019E  [SOT523]
R110  22R  [R0402]
R111  2.2K  [R0402]
R112  2.2K  [R0402]
R113  22R  [R0402]
R114  22R  [R0402]
R115  22R  [R0402]
R116  22R  [R0402]
R117  100K  [R0402]
R118  100K  [R0402]
R119  3.9R  [R0603]
R120  3.9R  [R0603]
R121  NC/10K  [R0402]
R122  NC/0R  [RN_0402X4]
R123  NC/0R  [RN_0402X4]
R126  NC/2.2R  [R0402]
R127  NC/2.2R  [R0402]
R132  NC/10K  [R0402]
R133  NC/10K  [R0402]
R134  100K  [R0402]
R135  0R  [R0402]
R136  10K  [R0402]
R137  1K  [R0402]
R138  0R  [R0402]
R408  NC/0R  [R0402]
R409  0R  [R0402]
R417  22R  [R0402]
U13  SY7201ABC  [SOT23-6]
U14  NC/74LVC1G125GW,125  [SOT353]
sheet P12. VI-MIPI-CSI
C95  NC/6.8pF  [C0402]
C96  100nF  [C0402]
C97  NC/6.8pF  [C0402]
C98  100nF  [C0402]
C99  100nF  [C0402]
C100  100nF  [C0402]
C101  10uF  [C0603]
C102  10uF  [C0603]
C103  100nF  [C0402]
C104  100nF  [C0402]
C105  10uF  [C0603]
C106  10uF  [C0603]
C107  100nF  [C0402]
C108  NC/18pF  [C0402]
C109  10uF  [C0603]
C110  10uF  [C0603]
C111  100nF  [C0402]
C253  1uF  [C0402]
C254  1uF  [C0402]
C255  1uF  [C0402]
D98  SE05NRC14GA  [DFN2510-10L]
D99  SE05NRC14GA  [DFN2510-10L]
D100  PE0402N12G01B  [V0402]
D101  PE0402N12G01B  [V0402]
D102  SE05NRC14GA  [DFN2510-10L]
D103  SE05NRC14GA  [DFN2510-10L]
D104  SE05NRC14GA  [DFN2510-10L]
D105  PE0402N12G01B  [V0402]
D106  PE0402N12G01B  [V0402]
J19  FPC05-PUW-24P  [FPC05-24P]
J20  FPC05-PUW-24P  [FPC05-24P]
Q16  MMFTN3019E  [SOT523]
Q17  MMFTN3019E  [SOT523]
R139  0R  [RN_0402X4]
R140  0R  [RN_0402X4]
R141  NC/0R  [RN_0402X4]
R147  2.2R  [R0402]
R148  2.2R  [R0402]
R149  22R  [R0402]
R150  22R  [R0402]
R151  22R  [R0402]
R152  22R  [R0402]
R153  22R  [R0402]
R154  2.2K  [R0402]
R155  2.2K  [R0402]
R156  10K  [R0402]
R157  2.2R  [R0402]
R158  2.2R  [R0402]
R159  NC/22R  [R0402]
R160  NC/22R  [R0402]
R161  10K  [R0402]
R162  10K  [R0402]
R163  100R  [R0402]
R164  22R  [R0402]
R165  22R  [R0402]
R166  10K  [R0402]
R172  24.9K  [R0402]
R173  20K  [R0402]
R175  17.4K  [R0402]
R176  20K  [R0402]
R177  49.9K  [R0402]
R179  20K  [R0402]
R416  22R  [R0402]
R421  120R  [R0402]
U15  ETA5050V0S2F  [SOT23-5]
U16  ETA5050V0S2F  [SOT23-5]
U17  ETA5050V0S2F  [SOT23-5]
sheet P14. Ethernet-GEPHY_RGMII0
C129  18pF  [C0402]
C130  18pF  [C0402]
C131  NC/6.8pF  [C0402]
C132  NC/100pF  [C0402]
C133  NC/100pF  [C0402]
C134  NC/6.8pF  [C0402]
C135  NC/6.8pF  [C0402]
C136  4.7uF  [C0402]
C137  100nF  [C0402]
C138  100nF  [C0402]
C139  100nF  [C0402]
C140  100nF  [C0402]
C141  100nF  [C0402]
C142  10nF  [C0402]
C143  100nF  [C0402]
C144  1uF  [C0402]
C145  1uF  [C0402]
C146  100nF  [C0402]
C147  NC/6.8pF  [C0402]
C148  4.7uF  [C0402]
C149  100nF  [C0402]
C150  100nF  [C0402]
C151  4.7uF  [C0402]
C152  100nF  [C0402]
D54  SE05D3L01GE  [SOD323]
D55  SE05D3L01GE  [SOD323]
D56  SE05D3L01GE  [SOD323]
D57  SE05D3L01GE  [SOD323]
D83  SRV05-4  [SOT23-6]
D84  SRV05-4  [SOT23-6]
J22  HR911130C  [RJ45-TH_HR911130A]
L22  2.2uH/1.9A  [IND_252012]
R211  510R  [R0402]
R213  510R  [R0402]
R214  2.2R  [R0402]
R215  2.2R  [R0402]
R216  100R  [R0402]
R219  120R  [R0402]
R220  2.2R  [R0402]
R221  2.2R  [R0402]
R222  2.2R  [R0402]
R223  2.2R  [R0402]
R224  22R  [R0402]
R225  NC/4.7K  [R0402]
R226  4.7K  [R0402]
R227  22R  [R0402]
R228  22R  [R0402]
R229  NC/4.7K  [R0402]
R230  4.7K  [R0402]
R231  22R  [R0402]
R232  22R  [R0402]
R233  4.7K  [R0402]
R234  22R  [R0402]
R235  4.7K  [R0402]
R236  4.7K  [R0402]
R237  4.7K  [R0402]
R238  NC/4.7K  [R0402]
R239  4.7K  [R0402]
R240  NC/4.7K  [R0402]
R241  2.49K  [R0402]
R242  4.7K  [R0402]
R243  NC/4.7K  [R0402]
R245  NC/4.7K  [R0402]
R246  4.7K  [R0402]
R248  0R  [R0402]
R249  1.8K  [R0402]
R250  0R  [R0402]
R252  22R  [R0402]
R253  22R  [R0402]
R254  22R  [R0402]
R255  22R  [R0402]
R256  22R  [R0402]
R257  22R  [R0402]
R258  0R  [R0402]
R424  2.2R  [R0402]
R425  2.2R  [R0402]
U19  RTL8211F-CG  [QFN-40_5x5x04P]
XT3  25MHz  [xtal_32x25_4p]

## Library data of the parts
C63 C64 C66 C71 C78 C80 C90 C144 C145 C253-C255 C258 C260 = C-0402: DSC1: ±10%; DSC2: 10V; DSC3: X5R; ERP Number: 1010200054; ID: 64; Manufacture: 三星|国巨|村田; Part Name: 贴片电容; Part Number: C020102120064; Price: 0.02
C65 = C-0402: DSC1: ±5%; DSC2: 50V; DSC3: C0G; ERP Number: 1010200149; ID: 45; Manufacture: 三星|国巨|村田; Part Name: 贴片电容; Part Number: C020102120045; Price: 0.01
C67 C68 C72 C75 C82 C85 C88 C96 C98-C100 C103 C104 C107 C111 C137-C141 C143 C146 C149 C150 C152 = C-0402: DSC1: ±10%; DSC2: 10V; DSC3: X7R; ID: 60; Manufacture: 三星|国巨|村田; Part Name: 贴片电容; Part Number: C020102120060; Price: 0.01
C73 C74 C76 C77 = C-0402: DSC1: ±10%; DSC2: 50V; DSC3: X7R; ERP Number: 1010200084; ID: 54; Manufacture: 三星|国巨|村田; Part Name: 贴片电容; Part Number: C020102120054; Price: 0.01
C248-C252 = C-0805: DSC1: ±20%; DSC2: 10V; DSC3: X5R; ID: 75; Manufacture: 三星|国巨|村田; Part Name: 贴片电容; Part Number: C020102120075; Price: 0.11
D27-D33 D36 D38 D44-D47 D52 D53 D97 D100 D101 D105 D106 = DI-ESD: DSC1: 双向; DSC2: Vdc=12V; DSC4: Vc=40V; DSC5: Cj=0.05pF; ID: 1; Manufacture: 硕凯; Part Name: ESD; Part Number: C040504013980; Price: 0.06; Solder: 推荐
J10 = J-PJ-326A-3P: DSC1: 3.5mm贴片式耳机座 凸头 3P 双定位柱; DSC2: 14*5.6*5.1mm; DSC4: PJ-326(星坤); ID: 11; Part Name: 音频耳机座; Part Number: J050502940003
J11 = J-H-2P: DSC1: 2p; DSC2: 2.0mm间距; DSC3: 通孔180度直针; DSC4: 米黄色胶壳 耐高温; DSC5: JLX-PH20-2A（九龙熹）; DSC6: X2016WV-02-46SN(星坤); ID: 11; Part Name: PH; Part Number: J020302820001
J12 = J-H-4P: DSC1: 4p; DSC2: 2.0mm间距; DSC3: 通孔180度直针; DSC4: 米黄色胶壳 耐高温; DSC5: JLX-PH20-4A（九龙熹）; DSC6: X2016WV-04-46SN(星坤); ID: 13; Part Name: PH; Part Number: J020302820003
L11-L14 = FB-0603: DSC1: 100Ω@100MHz; DSC2: 3A; DSC3: DCR=30mΩ; DSC4: 电源线; ERP Number: 1010200207; ID: 5; Manufacture: 顺络; Part Name: 贴片磁珠; Part Number: C060502370005; Price: 0.03
Q3-Q5 Q7 Q14-Q17 = N-MOS-Q: DSC1: Vds=30V; DSC2: Id=100mA; DSC3: Vgs(th)=1.5V; DSC4: Vgs=±20V; DSC5: pd=150mW; ERP Number: 1010800011; ID: 4; Manufacture: 先科; Part Name: N-MOS; Part Number: C030202190004; Price: 0.1
R80 R163 R216 = R-0402: DSC1: ±5%; DSC2: 1/16W; ERP Number: 1010200160; ID: 279; Part Name: 贴片电阻; Part Number: C011002080279; Price: 0.01
R81 R82 R84 R135 R138 R248 R250 R258 R408 R409 R413 R415 = R-0402: DSC1: ±5%; DSC2: 1/16W; ERP Number: 1010200100; ID: 217; Part Name: 贴片电阻; Part Number: C011002080217; Price: 0.01
R83 R225 R226 R229 R230 R233 R235-R240 R242 R243 R245 R246 = R-0402: DSC1: ±5%; DSC2: 1/16W; ERP Number: 1010200177; ID: 320; Part Name: 贴片电阻; Part Number: C011002080320; Price: 0.01
R85 = R-0603: DSC1: ±1%; DSC2: 1/10W; ERP Number: 1010200158; ID: 1,182; Part Name: 贴片电阻; Part Number: C011002081182; Price: 0.01
R86 = R-0805: DSC1: ±1%; DSC2: 1/8W; ERP Number: 1010200199; ID: 1,448; Part Name: 贴片电阻; Part Number: C011002081448; Price: 0.01
R87 R88 = R-0402: DSC1: ±5%; DSC2: 1/16W; ID: 340; Part Name: 贴片电阻; Part Number: C011002080340; Price: 0.01
R89 R90 R107 R137 = R-0402: DSC1: ±5%; DSC2: 1/16W; ERP Number: 1010200104; ID: 303; Part Name: 贴片电阻; Part Number: C011002080303; Price: 0.01
U11 = U-NS4205: DSC1: 2*3W @4Ω,3~5.2V，Class D; DSC3: -40~85℃; ERP Number: 1010100190; ID: 2; Manufacture: Nsiway(纳芯威); Part Name: 功放; Part Number: C150102670002; Price: 0.7
C79 C101 C102 C105 C106 C109 C110 = C-0603: DSC1: ±20%; DSC2: 10V; DSC3: X5R; ERP Number: 1010200076; ID: 71; Manufacture: 三星|国巨|村田; Part Name: 贴片电容; Part Number: C020102120071; Price: 0.05
C81 C84 C86 C87 C92 C94 = C-0603: DSC1: ±10%; DSC2: 50V; DSC3: X5R; ERP Number: 1010200142; ID: 69; Manufacture: 三星|国巨|村田; Part Name: 贴片电容; Part Number: C020102120069; Price: 0.04
C83 C89 C136 C148 C151 = C-0402: DSC1: ±20%; DSC2: 10V; DSC3: X5R; ID: 67; Manufacture: 三星|国巨|村田; Part Name: 贴片电容; Part Number: C020102120067; Price: 0.04
D34 D35 D37 D40 D41 D48 D49 D51 D98 D99 D102-D104 = DI-ESD-SE05NRC14GA: DSC1: 双向; DSC2: Vdc=5V; DSC3: Vbr=8V; DSC4: Vc=20V; DSC5: Cj=0.4pF; ID: 8; Manufacture: 硕凯; Part Name: ESD; Part Number: C040504013981; Price: 0.15; Solder: 推荐
D39 D50 = DI-XI-S: DSC1: VR=40V; DSC2: IF=3A; DSC3: VF=500mV/3A; ID: 7; Manufacture: 乐山无线电; Part Name: 肖特基二级管; Part Number: C040202220007; Price: 0.15; Solder: 推荐
J13 J15 = J-FPC-40P: DSC1: 40P; DSC2: 0.5mm间距; DSC3: 上接 抽拉式 卧贴; DSC4: H=2mm; DSC5: 镀锡; DSC6: X05B20U40T(星坤); ID: 10; Part Name: FPC座; Part Number: J030102870037
L15 L20 = L-IND: DSC1: ±20%; DSC2: Isat=1.6A; DSC3: Irms=1.25A; DSC4: 260mΩ; DSC5: 2.5*2.0*1.2mm; DSC6: WPN252012H4R7MT(顺络); DSC7: FHD252012S-4R7MT(长江微电); DSC8: ZCRH252012-4.7uH-M(宗成); ID: 54; Manufacture: 宗成|长江微电|顺络; Part Name: 功率电感
R91 R94-R97 R110 R113-R116 R149-R153 R159 R160 R164 R165 R224 R227 R228 R231 R232 R234 R252-R257 R416-R418 = R-0402: DSC1: ±5%; DSC2: 1/16W; ERP Number: 1010200173; ID: 262; Part Name: 贴片电阻; Part Number: C011002080262; Price: 0.01
R92 R93 R111 R112 R154 R155 = R-0402: DSC1: ±5%; DSC2: 1/16W; ERP Number: 1010200170; ID: 311; Part Name: 贴片电阻; Part Number: C011002080311; Price: 0.01
R98 R103 R105 R121 R132 R133 R136 R156 R161 R162 R166 = R-0402: DSC1: ±5%; DSC2: 1/16W; ERP Number: 1010200096; ID: 328; Part Name: 贴片电阻; Part Number: C011002080328; Price: 0.01
R99 R100 R108 R117 R118 R134 = R-0402: DSC1: ±5%; DSC2: 1/16W; ERP Number: 1010200103; ID: 353; Part Name: 贴片电阻; Part Number: C011002080353; Price: 0.01
R101 R102 R119 R120 = R-0603: DSC1: ±1%; DSC2: 1/10W; ID: 1,232; Part Name: 贴片电阻; Part Number: C011002081232; Price: 0.01
U12 U13 = U-SY7201A_2: DSC1: Vi=2.5-30V; DSC3: Io=2A; DSC4: Vfb=200mV; DSC5: 0.9; DSC6: 1MHz; DSC7: Boost LED驱动; ERP Number: 1010100053; ID: 24; Manufacture: 矽力杰; Part Name: DCDC; Part Number: C070202410024; Price: 1; Solder: 量产
D42 D43 = DI-XI-S: DSC1: VR=40V; DSC2: IF=1A; DSC3: VF=540mV/1A; DSC4: IR=3uA; ID: 17; Manufacture: 乐山无线电; Part Name: 肖特基二级管; Part Number: C040205134719; Price: 0.13
J14 = J-HDMI-19P: DSC1: HDMI 19P母座SMD铜壳四脚 黑胶LCP 耐高温; DSC2: 15*11.8*6mm; DSC3: 贴片; DSC4: JLX-HDMI-002（九龙熹）; DSC5: A71-05H9-111N1（星坤）; ID: 7; Part Name: HDMI座; Part Number: J050302920001
L16-L19 = L-CMLS-ACM2012: DSC1: 90uH@100kHz; DSC2: 90Ω@100MHz; DSC3: 400mA; DSC4: DCR=300mΩ; DSC5: -40℃ ~ +125℃; DSC6: SMD_4P,2x1.2mm; ERP Number: 1010200196; ID: 1; Manufacture: 台庆; Part Name: 信号共模电感; Part Number: C060402360001; Price: 0.13
R104 R106 R249 = R-0402: DSC1: ±5%; DSC2: 1/16W; ID: 309; Part Name: 贴片电阻; Part Number: C011002080309; Price: 0.01
R109 = R-0402: DSC1: ±5%; DSC2: 1/16W; ERP Number: 1010200461; ID: 338; Part Name: 贴片电阻; Part Number: C011002080338; Price: 0.01
C91 C93 C256 = C-0805: DSC1: ±10%; DSC2: 25V; DSC3: X5R; ERP Number: 1010200144; ID: 74; Manufacture: 三星|国巨|村田; Part Name: 贴片电容; Part Number: C020102120074; Price: 0.09
H2 = HOLE
J16 = J-HDR-D-20: DSC1: 双排单塑; DSC2: 2x10; DSC3: 2mm脚距; DSC4: 通孔弯针; DSC5: 2.8+2(H塑高)+4 mm; DSC6: 黑胶; DSC7: X4621WR-2x10I-C28D40（星坤）; ID: 29; Part Name: 双排针; Part Number: J010102760085
J17 = J-HDR-6: DSC1: 单排单塑; DSC2: 1x6; DSC3: 2mm脚距; DSC4: 通孔直针; DSC5: 针长8.8mm  2.8+2(H塑高)+4 mm; DSC6: 黑胶; DSC7: X4611WV-06I-C28D40（星坤）; ID: 66; Part Name: 单排针; Part Number: J010206123880
J18 = J-H-6P: DSC1: 6p; DSC2: 2.0mm间距; DSC3: 通孔180度直针; DSC4: 米黄色胶壳 耐高温; DSC5: JLX-PH20-6A（九龙熹）; DSC6: X2016WV-06-46SN(星坤); ID: 15; Part Name: PH; Part Number: J020302820005
J31 = J-FPC-6P: DSC1: 6P; DSC2: 0.5mm间距; DSC3: 下接 翻盖 卧贴; DSC4: H=2mm; DSC5: 镀锡; DSC6: X05A20L06T(星坤); ID: 13; Part Name: FPC座; Part Number: J030102870054
Q6 = P-MOS: DSC1: Vds=-30V; DSC2: Id=-4.2A; DSC3: Vgs(th)=1.3V; DSC4: Vgs=±12V; DSC5: pd=350mW; ERP Number: 1010800001; ID: 1; Manufacture: 长电; Part Number: C030202190001; Price: 0.17
Q8 = N-MOS-Q: DSC1: Vds=30V; DSC2: Id=100mA; DSC3: Vgs(th)=1.5V; DSC4: Vgs=±20V; DSC5: pd=150mW; ERP Number: 1010800011; Manufacture: 先科; Part Name: N-MOS; Part Number: C030202190004; Price: 0.1
R122 R123 R139-R141 = RN_0402X4: DSC1: ±5%; DSC2: 1/16W; ID: 1; Part Name: 贴片排阻; Part Number: C010302090001; Price: 0.01
R126 R127 R147 R148 R157 R158 R214 R215 R220-R223 R424 R425 = R-0402: DSC1: ±5%; DSC2: 1/16W; ERP Number: 1010200263; ID: 238; Part Name: 贴片电阻; Part Number: C011002080238; Price: 0.01
U14 = U-74LVC1G125GW-125: DSC1: 1位 高速缓冲 三态输出 VCC=1.65V-5.5V; DSC2: SOT-353; DSC3: -55℃~+125℃; ERP Number: 1010100128; ID: 5; Manufacture: Nexperia(安世); Part Name: 逻辑缓冲器; Part Number: C080302460001; Price: 0.13
C95 C97 C131 C134 C135 C147 = C-0402: DSC1: ±0.25PF; DSC2: 50V; DSC3: C0G; ERP Number: 1010200056; ID: 18; Manufacture: 三星|国巨|村田; Part Name: 贴片电容; Part Number: C020102120018; Price: 0.01
C108 C129 C130 = C-0402: DSC1: ±5%; DSC2: 50V; DSC3: C0G; ERP Number: 1010200091; ID: 27; Manufacture: 三星|国巨|村田; Part Name: 贴片电容; Part Number: C020102120027; Price: 0.02
J19 J20 = J-FPC-24P: DSC1: 24P; DSC2: 0.5mm间距; DSC3: 上接 抽拉式 卧贴; DSC4: H=2mm; DSC5: 镀锡; DSC6: X05B20U24T(星坤); ID: 34; Part Name: FPC座; Part Number: J030102870021
R172 = R-0402: DSC1: ±1%; DSC2: 1/16W; ERP Number: 1010200327; ID: 900; Part Name: 贴片电阻; Part Number: C011002080900; Price: 0.01
R173 R176 R179 = R-0402: DSC1: ±1%; DSC2: 1/16W; ERP Number: 1010200333; ID: 889; Part Name: 贴片电阻; Part Number: C011002080889; Price: 0.01
R175 = R-0402: DSC1: ±1%; DSC2: 1/16W; ID: 882; Part Name: 贴片电阻; Part Number: C011002080882; Price: 0.01
R177 = R-0402: DSC1: ±1%; DSC2: 1/16W; ID: 938; Part Name: 贴片电阻; Part Number: C011002080938; Price: 0.01
R219 R421 = R-0402: DSC1: ±5%; DSC2: 1/16W; ID: 281; Part Name: 贴片电阻; Part Number: C011002080281; Price: 0.01
U15-U17 = U-ETA5050: DSC1: Vi=2.5-5.5V; DSC2: Vo=adj; DSC3: Io=500mA; DSC5: Iq=40uA; ID: 28; Manufacture: ETA; Part Name: LDO; Part Number: C070111104620; Solder: 推荐
C132 C133 = C-0402: DSC1: ±5%; DSC2: 50V; DSC3: C0G; ERP Number: 1010200152; ID: 40; Manufacture: 三星|国巨|村田; Part Name: 贴片电容; Part Number: C020102120040; Price: 0.01
C142 = C-0402: DSC1: ±10%; DSC2: 50V; DSC3: X7R; ERP Number: 1010200077; ID: 57; Manufacture: 三星|国巨|村田; Part Name: 贴片电容; Part Number: C020102120057; Price: 0.02
D54-D57 = DI-TVS-D: DSC1: 双向; DSC2: Vdc=5V; DSC4: Vc=19V; DSC5: Cj=1.2pF; ID: 10; Manufacture: 硕凯; Part Name: ESD; Part Number: C040505124709; Price: 0.06; Solder: 推荐
D83 D84 = DI-ESD-SRV05-4: DSC1: 单向; DSC2: Vrwm=5V; DSC3: VBR=6V; DSC4: Vc=13V; DSC5: Ipp=3.5A; DSC6: Ppp=45W; DSC7: Cj=0.36pF; ERP Number: 1010800050; ID: 15; Manufacture: 伯恩半导体; Part Name: TVS; Part Number: C040602260015; Price: 0.21; Solder: 量产
J22 = J-RJ45-HR911130C: DSC1: RJ45 8P插件 内置千兆变压器(商业级)  双灯 卧式 全包带弹片,16x21.3x13.5mm; DSC2: 通孔弯针; DSC4: HR911130C(汉仁); ID: 5; Part Name: RJ45; Part Number: J120103060005
L22 = L-IND: DSC1: ±20%; DSC2: Isat=2.6A; DSC3: Irms=1.9A; DSC4: 120mΩ; DSC5: 2.5*2.0*1.2mm; DSC6: WPN252012H2R2MT(顺络); DSC7: FHD252012S-2R2MT(长江微电); DSC8: ZCRH252012-2.2uH-M(宗成); ID: 53; Manufacture: 宗成|长江微电|顺络; Part Name: 功率电感
R211 R213 = R-0402: DSC1: ±5%; DSC2: 1/16W; ERP Number: 1010200226; ID: 296; Part Name: 贴片电阻; Part Number: C011002080296; Price: 0.01
R241 = R-0402: DSC1: ±1%; DSC2: 1/16W; ERP Number: 1010200324; ID: 785; Part Name: 贴片电阻; Part Number: C011002080785; Price: 0.01
U19 = Ethernet_RTL8211F: Integrated 10/100/1000 Gigabit Ethernet Transceiver，Supports IEEE 802.3az-2010,; Created by: JJJ; Manufacturer: RealTek(瑞昱); Part Type: Ethernet; Priority: A
XT3 = XTAL-4P: DSC1: 40Ω; DSC2: ±10ppm; DSC3: 12pF; DSC4: -40℃~+85℃; DSC5: 3.2*2.5mm 4P; ID: 6; Manufacture: 泰晶; Part Name: 贴片无源晶振; Part Number: C050102290006; Price: 0.48

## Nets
GND: C63.2 C65.1 C66.1 C67.1 C68.1 C71.1 C73.2 C74.2 C76.2 C77.2 C78.1 C79.1 C80.1 C81.1 C82.1 C83.1 C84.1 C85.1 C86.1 C87.1 C88.1 C89.1 C90.1 C91.1 C93.1 C94.1 C95.1 C96.1 C97.1 C98.1 C99.1 C100.1 C101.1 C102.1 C103.1 C104.1 C105.1 C106.1 C107.1 C109.1 C110.1 C111.1 C129.1 C130.1 C131.1 C132.1 C133.1 C134.1 C135.1 C136.1 C137.1 C138.1 C139.1 C140.1 C141.1 C142.1 C143.1 C144.1 C145.1 C146.1 C147.1 C148.1 C149.1 C150.1 C151.1 C152.1 C248.1 C249.1 C250.1 C251.1 C252.1 C253.1 C254.1 C255.1 C258.1 C260.1 D27.1(I/O2) D28.1(I/O2) D29.1(I/O2) D30.1(I/O2) D31.1(I/O2) D32.1(I/O2) D33.1(I/O2) D34.3 D34.8 D35.3 D35.8 D36.2(I/O1) D37.3 D37.8 D38.2(I/O1) D40.3 D40.8 D41.3 D41.8 D44.2(I/O1) D45.2(I/O1) D46.2(I/O1) D47.2(I/O1) D48.3 D48.8 D49.3 D49.8 D51.3 D51.8 D52.2(I/O1) D53.2(I/O1) D83.2 D84.2 D97.1(I/O2) D98.3 D98.8 D99.3 D99.8 D100.2(I/O1) D101.2(I/O1) D102.3 D102.8 D103.3 D103.8 D104.3 D104.8 D105.2(I/O1) D106.2(I/O1) H2.1 J11.2 J13.11 J13.16 J13.18 J13.19 J13.22 J13.25 J13.28 J13.31 J13.34 J13.37 J13.41 J13.42 J14.2 J14.5 J14.8 J14.11 J14.14 J14.17 J14.20 J14.21 J14.22 J14.23 J15.11 J15.16 J15.18 J15.19 J15.22 J15.25 J15.28 J15.31 J15.34 J15.37 J15.41 J15.42 J16.5 J16.6 J16.13 J16.14 J19.10 J19.13 J19.16 J19.19 J19.22 J19.25 J19.26 J20.10 J20.13 J20.16 J20.19 J20.22 J20.25 J20.26 J22.10(GND) J31.6 J31.7 J31.8 Q8.2(SOURCE) Q14.2(SOURCE) Q15.2(SOURCE) R81.2 R100.1 R101.1 R102.1 R108.1 R118.1 R119.1 R120.1 R173.1 R176.1 R179.1 R213.2 R219.1 R225.1 R229.1 R233.1 R235.1 R237.1 R239.1 R241.1 R242.1 R245.1 R421.1 U11.2(PGND1) U11.11(GND1) U11.15(PGND2) U12.2(GND) U13.2(GND) U14.1(~{OE}) U14.3(GND) U15.2(GND) U16.2(GND) U17.2(GND) U19.41(E_Pad) XT3.2 XT3.4 ; also on sheet 4 5 6 7 14 15 16 17 18 19 20
GND_EARTH: J22.SH1 J22.SH2 ; also on sheet 4 14
GND_IN: C256.1 J18.1 J18.2 ; also on sheet 4 17
VCC1V5_DVP: C100.2 C106.2 C107.2 C108.1 C254.2 J19.3 J20.3 R175.2 U16.5(VOUT)
VCC1V8_DVP: C102.2 C103.2 C104.2 C255.2 J19.4 J20.4 Q16.1(GATE) Q17.1(GATE) R156.2 R161.2 R162.2 R166.2 R172.2 U15.5(VOUT)
VCC2V8_DVP: C98.2 C110.2 C111.2 C253.2 J19.1 J19.2 J20.1 J20.2 R177.2 U17.5(VOUT)
VCC3V3_PHY0: C148.2 C149.2 C150.2 C151.2 C152.2 R211.2 R226.2 R230.2 R258.2 U19.11(AVDD33) U19.29(DVDD33) U19.40(AVDD33)
VCC5V_HDMI_TX: C85.2 D43.C J14.18
VCC5V_SPK: C249.2 C250.2 C251.2 C252.2 R86.2 U11.4(PVDD1) U11.13(PVDD2)
VCC5V_SYS: D42.A D43.A Q5.1(GATE) ; also on sheet 4 5
VCC12V_DCIN: C256.2 J17.1 J18.5 J18.6 ; also on sheet 4 17
VCC_1V8: R154.2 R155.2 R250.1 R408.1 R413.1 ; also on sheet 5 7 14 15 20
VCC_5V: C82.2 C83.2 C88.2 C89.2 C94.2 C248.2 J17.3 L15.1 L20.1 Q7.1(GATE) R86.1 R133.1 U12.6(VIN) U13.6(VIN) U14.5(Vcc) ; also on sheet 4 7 15 17 18
VCC_LEDA_TX0: C86.2 C87.2 D50.C J15.1 J15.2 U13.5(OVP)
VCC_LEDA_TX1: C81.2 C84.2 D39.C J13.1 J13.2 U12.5(OVP)
VCC_LEDK_TX0: J15.9 J15.10 R117.1 R119.2 R120.2
VCC_LEDK_TX1: J13.9 J13.10 R99.1 R101.2 R102.2
VCC_LVDS_OUT: C91.2 C92.2 J17.2 J17.4 J17.6 Q6.2(SOURCE) R134.2
VCC_LVDS_OUT_: C93.2 J16.1 J16.2 J16.3 Q6.3(DRAIN)
VCCA_CODEC: C67.2 C68.2 R85.2 U11.6(VDD1) U11.9(VDD2)
VCCIO_PHY0: C144.2 C145.2 C146.2 R236.2 R238.2 R240.2 R243.2 R246.2 R249.2 R250.2 U19.28(DVDD_RG)
VDD10_PHY0: C136.2 C137.2 C138.2 C139.2 C140.2 C141.2 L22.2 U19.3(AVDD10) U19.8(AVDD10) U19.21(DVDD10) U19.38(AVDD10)
VDD_3V3: C79.2 C101.2 C105.2 C109.2 C260.2 J13.38 J13.39 J15.38 J15.39 J17.5 J31.1 Q3.1(GATE) Q4.1(GATE) R80.1 R85.1 R92.2 R93.2 R98.1 R103.1 R105.1 R109.2 R111.2 R112.2 R121.1 R132.1 R258.1 R409.1 R415.1 U15.1(VIN) U16.1(VIN) U17.1(VIN) ; also on sheet 4 7 14 15 16 17 19 20
CAM0_PDN_H_GPIO1_D0: R150.1 ; also on sheet 5
CAM0_RST_L__GPIO1_D1: R151.1 ; also on sheet 5
CAM1_PDN_H_GPIO1_D2: R164.1 ; also on sheet 5
CAM1_RST_L_GPIO1_C7: R165.1 ; also on sheet 5
CAM_CLKOUT0: R163.1 ; also on sheet 5
CAMERA_PWREN: R416.2 U15.3(EN) U16.3(EN) U17.3(EN)
CAMERA_PWREN_GPIO4_D2: R416.1 ; also on sheet 5
CIF_CLK0: C95.2 D102.5 D102.6 J19.9 R149.2
CIF_CLK1: C97.2 D103.5 D103.6 J20.9 R163.2 R421.2
CIF_CLKOUT_SOC: R149.1 ; also on sheet 5
CIF_PDN0: D102.1 D102.10 J19.6 R150.2
CIF_PDN1: D103.1 D103.10 J20.6 R164.2
CIF_RST0: C96.2 J19.5 R151.2 R156.1
CIF_RST1: C99.2 J20.5 R165.2 R166.1
GMAC0_MCLKINOUT: C131.2 R216.1 R219.2 ; also on sheet 5
GMAC0_MDC: U19.13(MDC) ; also on sheet 5
GMAC0_MDIO: R249.1 U19.14(MDIO) ; also on sheet 5
GMAC0_RSTn_GPIO2_D5: R248.1 ; also on sheet 5
GMAC0_RXCLK: C147.2 R256.2 ; also on sheet 5
GMAC0_RXD0: R252.2 ; also on sheet 5
GMAC0_RXD1: R253.2 ; also on sheet 5
GMAC0_RXD2: R254.2 ; also on sheet 5
GMAC0_RXD3: R255.2 ; also on sheet 5
GMAC0_RXDV_CRS: R257.2 ; also on sheet 5
GMAC0_TXCLK: C134.2 R234.1 ; also on sheet 5
GMAC0_TXCLK_: C135.2 R234.2 U19.20(TXC)
GMAC0_TXD0: R224.1 ; also on sheet 5
GMAC0_TXD0_: R224.2 U19.18(TXD0)
GMAC0_TXD1: R227.1 ; also on sheet 5
GMAC0_TXD1_: R227.2 U19.17(TXD1)
GMAC0_TXD2: R228.1 ; also on sheet 5
GMAC0_TXD2_: R228.2 U19.16(TXD2)
GMAC0_TXD3: R231.1 ; also on sheet 5
GMAC0_TXD3_: R231.2 U19.15(TXD3)
GMAC0_TXEN: R232.1 ; also on sheet 5
GMAC0_TXEN_: R232.2 U19.19(TXCTL)
HDMI_TX_CEC_PORT: D44.1(I/O2) J14.13 Q5.3(DRAIN)
HDMI_TX_CLKN: L19.2 ; also on sheet 5
HDMI_TX_CLKN_: D41.5 D41.6 J14.12 L19.3
HDMI_TX_CLKP: L19.1 ; also on sheet 5
HDMI_TX_CLKP_: D41.4 D41.7 J14.10 L19.4
HDMI_TX_D0N: L18.2 ; also on sheet 5
HDMI_TX_D0N_: D41.2 D41.9 J14.9 L18.3
HDMI_TX_D0P: L18.1 ; also on sheet 5
HDMI_TX_D0P_: D41.1 D41.10 J14.7 L18.4
HDMI_TX_D1N: L17.2 ; also on sheet 5
HDMI_TX_D1N_: D40.5 D40.6 J14.6 L17.3
HDMI_TX_D1P: L17.1 ; also on sheet 5
HDMI_TX_D1P_: D40.4 D40.7 J14.4 L17.4
HDMI_TX_D2N: L16.2 ; also on sheet 5
HDMI_TX_D2N_: D40.2 D40.9 J14.3 L16.3
HDMI_TX_D2P: L16.1 ; also on sheet 5
HDMI_TX_D2P_: D40.1 D40.10 J14.1 L16.4
HDMI_TX_HPD_PORT: D46.1(I/O2) J14.19 R107.2 R108.2
HDMI_TX_HPDIN: R107.1 ; also on sheet 5
HDMI_TXDDC_SCL_PORT: D45.1(I/O2) J14.15 Q3.3(DRAIN) R104.1
HDMI_TXDDC_SDA_PORT: D47.1(I/O2) J14.16 Q4.3(DRAIN) R106.2
HDMITX_CEC_M0: Q5.2(SOURCE) R109.1 ; also on sheet 5
HP_SNS: J10.1(COM) R81.1 ; also on sheet 5
HPL_OUT: C72.2 R84.1 ; also on sheet 5
HPR_OUT: C75.2 R82.1 ; also on sheet 5
I2C2_SCL_M0: R111.1 R115.1 ; also on sheet 5
I2C2_SDA_M0: R112.1 R116.1 ; also on sheet 5
I2C3_SCL_M1: R92.1 R96.1 ; also on sheet 5
I2C3_SDA_M1: R93.1 R97.1 ; also on sheet 5
I2C4_SCL_M0: R152.1 R155.1 ; also on sheet 5
I2C4_SDA_M0: R153.1 R154.1 ; also on sheet 5
I2C5_SCL-HDMI: Q3.2(SOURCE) R103.2 ; also on sheet 5
I2C5_SCL_M0: Q17.3(DRAIN) ; also on sheet 5 19
I2C5_SDA-HDMI: Q4.2(SOURCE) R105.2 ; also on sheet 5
I2C5_SDA_M0: Q16.3(DRAIN) ; also on sheet 5 19
LAN0_A+: D57.A(I/O2) D84.4 J22.2(MDI_0+) R223.2
LAN0_A-: D57.C(I/O1) D84.3 J22.3(MDI_0-) R222.2
LAN0_B+: D56.A(I/O2) D84.6 J22.4(MDI_1+) R221.2
LAN0_B-: D56.C(I/O1) D84.1 J22.7(MDI_1-) R220.2
LAN0_C+: D55.A(I/O2) D83.4 J22.5(MDI_2+) R425.2
LAN0_C-: D55.C(I/O1) D83.3 J22.6(MDI_2-) R424.2
LAN0_D+: D54.A(I/O2) D83.6 J22.8(MDI_3+) R215.2
LAN0_D-: D54.C(I/O1) D83.1 J22.9(MDI_3-) R214.2
LVDS_EN_GPIO3_A2: R137.2 ; also on sheet 5
LVDS_ON_: J18.4 Q7.2(SOURCE) R133.2 R135.2
LVDS_ON_GPIO3_A1: Q7.3(DRAIN) R132.2 R135.1 ; also on sheet 5
LVDS_PWM13: J18.3 R138.2 U14.4(Y)
LVDS_TX0_CLKN: J16.15 R127.2
LVDS_TX0_CLKP: J16.16 R126.2
LVDS_TX0_D0N: J16.7 R122.8
LVDS_TX0_D0P: J16.8 R122.7
LVDS_TX0_D1N: J16.9 R122.6
LVDS_TX0_D1P: J16.10 R122.5
LVDS_TX0_D2N: J16.11 R123.8
LVDS_TX0_D2P: J16.12 R123.7
LVDS_TX0_D3N: J16.17 R123.6
LVDS_TX0_D3P: J16.18 R123.5
MIC1_INN: C66.2 D97.2(I/O1) ; also on sheet 5
MIC1_INP: C64.2 ; also on sheet 5
MIPI_CSI_CLK0N: D99.1 D99.10 J19.17 R148.2
MIPI_CSI_CLK0P: D99.2 D99.9 J19.18 R147.2
MIPI_CSI_CLK1N: D105.1(I/O2) J20.17 R158.2
MIPI_CSI_CLK1P: D106.1(I/O2) J20.18 R157.2
MIPI_CSI_D0N: D98.1 D98.10 J19.11 R139.8
MIPI_CSI_D0P: D98.2 D98.9 J19.12 R139.7
MIPI_CSI_D1N: D98.4 D98.7 J19.14 R139.6
MIPI_CSI_D1P: D98.5 D98.6 J19.15 R139.5
MIPI_CSI_D2N: D99.4 D99.7 J19.20 R140.8
MIPI_CSI_D2N_: D104.1 D104.10 J20.11 R141.5
MIPI_CSI_D2P: D99.5 D99.6 J19.21 R140.7
MIPI_CSI_D2P_: D104.2 D104.9 J20.12 R141.6
MIPI_CSI_D3N: D100.1(I/O2) J19.23 R140.6
MIPI_CSI_D3N_: D104.4 D104.7 J20.14 R141.7
MIPI_CSI_D3P: D101.1(I/O2) J19.24 R140.5
MIPI_CSI_D3P_: D104.5 D104.6 J20.15 R141.8
MIPI_CSI_RX_CLK0N: R148.1 ; also on sheet 5
MIPI_CSI_RX_CLK0P: R147.1 ; also on sheet 5
MIPI_CSI_RX_CLK1N: R158.1 ; also on sheet 5
MIPI_CSI_RX_CLK1P: R157.1 ; also on sheet 5
MIPI_CSI_RX_D0N: R139.1 ; also on sheet 5
MIPI_CSI_RX_D0P: R139.2 ; also on sheet 5
MIPI_CSI_RX_D1N: R139.3 ; also on sheet 5
MIPI_CSI_RX_D1P: R139.4 ; also on sheet 5
MIPI_CSI_RX_D2N: R140.1 R141.4 ; also on sheet 5
MIPI_CSI_RX_D2P: R140.2 R141.3 ; also on sheet 5
MIPI_CSI_RX_D3N: R140.3 R141.2 ; also on sheet 5
MIPI_CSI_RX_D3P: R140.4 R141.1 ; also on sheet 5
MIPI_DSI_TX0_CLKN: D51.2 D51.9 J15.27 R127.1 ; also on sheet 5
MIPI_DSI_TX0_CLKP: D51.1 D51.10 J15.26 R126.1 ; also on sheet 5
MIPI_DSI_TX0_D0N: D53.1(I/O2) J15.33 R122.1 ; also on sheet 5
MIPI_DSI_TX0_D0P: D52.1(I/O2) J15.32 R122.2 ; also on sheet 5
MIPI_DSI_TX0_D1N: D51.5 D51.6 J15.30 R122.3 ; also on sheet 5
MIPI_DSI_TX0_D1P: D51.4 D51.7 J15.29 R122.4 ; also on sheet 5
MIPI_DSI_TX0_D2N: D49.5 D49.6 J15.24 R123.1 ; also on sheet 5
MIPI_DSI_TX0_D2P: D49.4 D49.7 J15.23 R123.2 ; also on sheet 5
MIPI_DSI_TX0_D3N: D49.2 D49.9 J15.21 R123.3 ; also on sheet 5
MIPI_DSI_TX0_D3P: D49.1 D49.10 J15.20 R123.4 ; also on sheet 5
MIPI_DSI_TX0_RST: C90.2 J15.36 R121.2 R417.2
MIPI_DSI_TX0_RST_GPIO4_C3: R417.1 ; also on sheet 5
MIPI_DSI_TX1_CLKN: D37.2 D37.9 J13.27 ; also on sheet 5
MIPI_DSI_TX1_CLKP: D37.1 D37.10 J13.26 ; also on sheet 5
MIPI_DSI_TX1_D0N: D38.1(I/O2) J13.33 ; also on sheet 5
MIPI_DSI_TX1_D0P: D36.1(I/O2) J13.32 ; also on sheet 5
MIPI_DSI_TX1_D1N: D37.5 D37.6 J13.30 ; also on sheet 5
MIPI_DSI_TX1_D1P: D37.4 D37.7 J13.29 ; also on sheet 5
MIPI_DSI_TX1_D2N: D35.5 D35.6 J13.24 ; also on sheet 5
MIPI_DSI_TX1_D2P: D35.4 D35.7 J13.23 ; also on sheet 5
MIPI_DSI_TX1_D3N: D35.2 D35.9 J13.21 ; also on sheet 5
MIPI_DSI_TX1_D3P: D35.1 D35.10 J13.20 ; also on sheet 5
MIPI_DSI_TX1_RST: C80.2 J13.36 R98.2 R418.2
MIPI_TX0_BL_PWM13: R110.2 R118.2 R138.1 U13.4(EN) U14.2(A)
MIPI_TX1_BL_PWM12: R91.2 R100.2 U12.4(EN)
MIPI_TX1_BL_PWM12_M0: R91.1 ; also on sheet 5
MIPI_TX1_RST_GPIO2_D6: R418.1 ; also on sheet 5
PHY0_CLKOUT125: R216.2 U19.35(CLKOUT)
PHY0_G_LED-: J22.12(G_LED-) R213.1
PHY0_LED0/CFG_EXT: R225.2 R226.1 U19.32(LED0/CFG_EXT)
PHY0_LED1/CFG_LDO0: C133.2 J22.11(G_LED+) R233.2 U19.33(LED1/CFG_LDO0)
PHY0_LED2/CFG_LDO1: C132.2 J22.13(Y_LED-) R229.2 R230.1 U19.34(LED2/CFG_LDO1)
PHY0_MDI0+: R223.1 U19.1(MDI[0]+)
PHY0_MDI0-: R222.1 U19.2(MDI[0]-)
PHY0_MDI1+: R221.1 U19.4(MDI[1]+)
PHY0_MDI1-: R220.1 U19.5(MDI[1]-)
PHY0_MDI2+: R425.1 U19.6(MDI[2]+)
PHY0_MDI2-: R424.1 U19.7(MDI[2]-)
PHY0_MDI3+: R215.1 U19.9(MDI[3]+)
PHY0_MDI3-: R214.1 U19.10(MDI[3]-)
PHY0_REG_OUT: L22.1 U19.30(REG_OUT)
PHY0_RSTn: C143.2 R248.2 U19.12(PHYRSTB)
PHY0_RXCLK/PHYAD1: R237.2 R238.1 R256.1 U19.27(RXC/PHYAD1)
PHY0_RXD0/RXDLY: R239.2 R240.1 R252.1 U19.25(RXD0/RXDLY)
PHY0_RXD1/TXDLY: R242.2 R243.1 R253.1 U19.24(RXD1/TXDLY)
PHY0_RXD2/PLLOFF: R245.2 R246.1 R254.1 U19.23(RXD2/PLLOFF)
PHY0_RXD3/PHYAD0: R236.1 R255.1 U19.22(RXD3/PHYAD0)
PHY0_RXDV/PHYAD2: R235.2 R257.1 U19.26(RXCTL/PHYAD2)
PHY0_XTALIN: C130.2 U19.36(XTAL_IN) XT3.3
PHY0_XTALOUT: C129.2 U19.37(XTAL_OUT/EXT_CLK) XT3.1
PHY0_Y_LED+: J22.14(Y_LED+) R211.1
PWM13_M1: R110.1 ; also on sheet 5
RSET0: R241.2 U19.39(RSET)
SCL_CAM0: D102.2 D102.9 J19.7 R152.2 R159.1
SCL_CAM1: D103.2 D103.9 J20.7 Q17.2(SOURCE) R159.2 R162.1
SDA_CAM0: D102.4 D102.7 J19.8 R153.2 R160.1
SDA_CAM1: D103.4 D103.7 J20.8 Q16.2(SOURCE) R160.2 R161.1
SPK_CTL_H_GPIO3_B0: R89.1 ; also on sheet 5
SPK_MUTE_H_GPIO3_A7: R90.1 ; also on sheet 5
TP0_INT: D48.4 D48.7 J15.5 J31.3 R114.2
TP0_INT_L_GPIO3_A3: R114.1 ; also on sheet 5
TP0_RST: D48.5 D48.6 J15.4 J31.2 R113.2
TP0_RST_L_GPIO3_A4: R113.1 ; also on sheet 5
TP0_SCL: D48.2 D48.9 J15.6 J31.4 R115.2
TP0_SDA: D48.1 D48.10 J15.7 J31.5 R116.2
TP1_INT: D34.2 D34.9 J13.5 R95.2
TP1_INT_L_GPIO3_C0: R95.1 ; also on sheet 5
TP1_RST: D34.1 D34.10 J13.4 R94.2
TP1_RST_L_GPIO3_C1: R94.1 ; also on sheet 5
TP1_SCL: D34.4 D34.7 J13.6 R96.2
TP1_SDA: D34.5 D34.6 J13.7 R97.2
VOLN: C73.1 D30.2(I/O1) J12.1 L11.2
VOLP: C74.1 D31.2(I/O1) J12.2 L12.2
VORN: C76.1 D32.2(I/O1) J12.3 L13.2
VORP: C77.1 D33.2(I/O1) J12.4 L14.2
N69844387: C63.1 R80.2 R83.2
N69844453: C64.1 C65.2 D29.2(I/O1) J11.1 R83.1
N69844782: D27.2(I/O1) J10.2(R) R82.2
N69844789: D28.2(I/O1) J10.3(L) R84.2
N69846177: C72.1 R87.1
N69846180: R87.2 U11.7(INL)
N69846237: C75.1 R88.1
N69846239: R88.2 U11.10(INR)
N69846282: C71.2 U11.8(Bypass)
N69846442: Q14.3(DRAIN) U11.5(~{MUTE})
N69846447: Q15.3(DRAIN) U11.12(~{SD})
N69846810: L11.1 U11.3(VOLN)
N69846813: L12.1 U11.1(VOLP)
N69846816: L13.1 U11.14(VORN)
N69846819: L14.1 U11.16(VORP)
N69847759: D42.C R104.2 R106.1
N69857283: R172.1 R173.2 U15.4(ADJ)
N69857307: C108.2 R175.1 R176.2 U16.4(ADJ)
N69857397: R177.1 R179.2 U17.4(ADJ)
N69873113: C142.2 J22.1(CT1/2/3/4)
N69911722: R99.2 U12.3(FB)
N69911786: C78.2 J13.17 R413.2 R415.2
N69912226: D39.A L15.2 U12.1(LX)
N69922645: R117.2 U13.3(FB)
N69922778: D50.A L20.2 U13.1(LX)
N69927169: C92.1 Q6.1(GATE) R134.1 R136.1
N69927197: Q8.3(DRAIN) R136.2
N69927388: Q8.1(GATE) R137.1
N70033042: Q15.1(GATE) R89.2
N70033056: Q14.1(GATE) R90.2
N70059784: C258.2 J15.17 R408.2 R409.2

Not connected (* = marked no-connect by the designer): D83 5*; D84 5*; J13 3 8 12 13 14 15 35 40; J15 3 8 12 13 14 15 35 40; J16 4 19 20; J20 20 21 23 24; U19 31(INTB/PMEB)

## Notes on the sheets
sheet 8
- MIC
- HP
- SPK
sheet 9
- MIPI_DSI_TX1
sheet 10
- HDMI A Type Port
- HDMI TX DDC
- HDMI TX HPD
- HDMI TX CEC
- Note:Option for CEC support.
- Note:Option for CEC support.
sheet 11
- MIPI_TX0
- LVDS
- Backlight Power
sheet 12
- 4 lanes or 2 lanes
- MIPI_CSI
- 2 lanes
sheet 13
- Giga PHY0
- RGMII Power Source
- CFG_EXT
- CFG_LDO[1:0]
- External 3.3V
- 1'b1
- 2'b00
- External 1.8V
- 1'b1
- 2'b10
- Internal 1.8V (default)
- 1'b0
- 2'b10
- 3.3Vpp
- Reserve for EMI.
- Reserve for EMI.
- MAC <----- PHY
- VCC_PHY0_IO Voltage Config
- Close to SOC
- PHY Address Config
- PHY Address
- PHYAD[2:0]
- 1 (default)
- 3'b001
- Pull-up for additional 2ns delay to RXC for data latching
- Pull-up for additional 2ns delay to TXC for data latching
- Pull-up to disable PLL @ ALDPS mode(Low power mode)
- Close to PIN21
- Close to PIN30
- RTL8211F-CG(SW Mode)
- RTL8211FI-CG(SW Mode)Industrial
- Close to PIN3,8,38
- RTL8211F-CG(SW Mode)
- RTL8211FI-CG(SW Mode)Industrial
- Note:
- According to the actual
  choice of mounted
  Cannot be mounted
  at the same time
- PHYRSTB is 3.3V IO
- Close to PIN28
- Close to PIN11,40
- Close to PHY
- Close to PIN29
